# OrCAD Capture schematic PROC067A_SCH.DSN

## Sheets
1 07. HARDWARE SCHEMATICS: title: HARDWARE SCHEMATICS; rev: A; note: PROC066
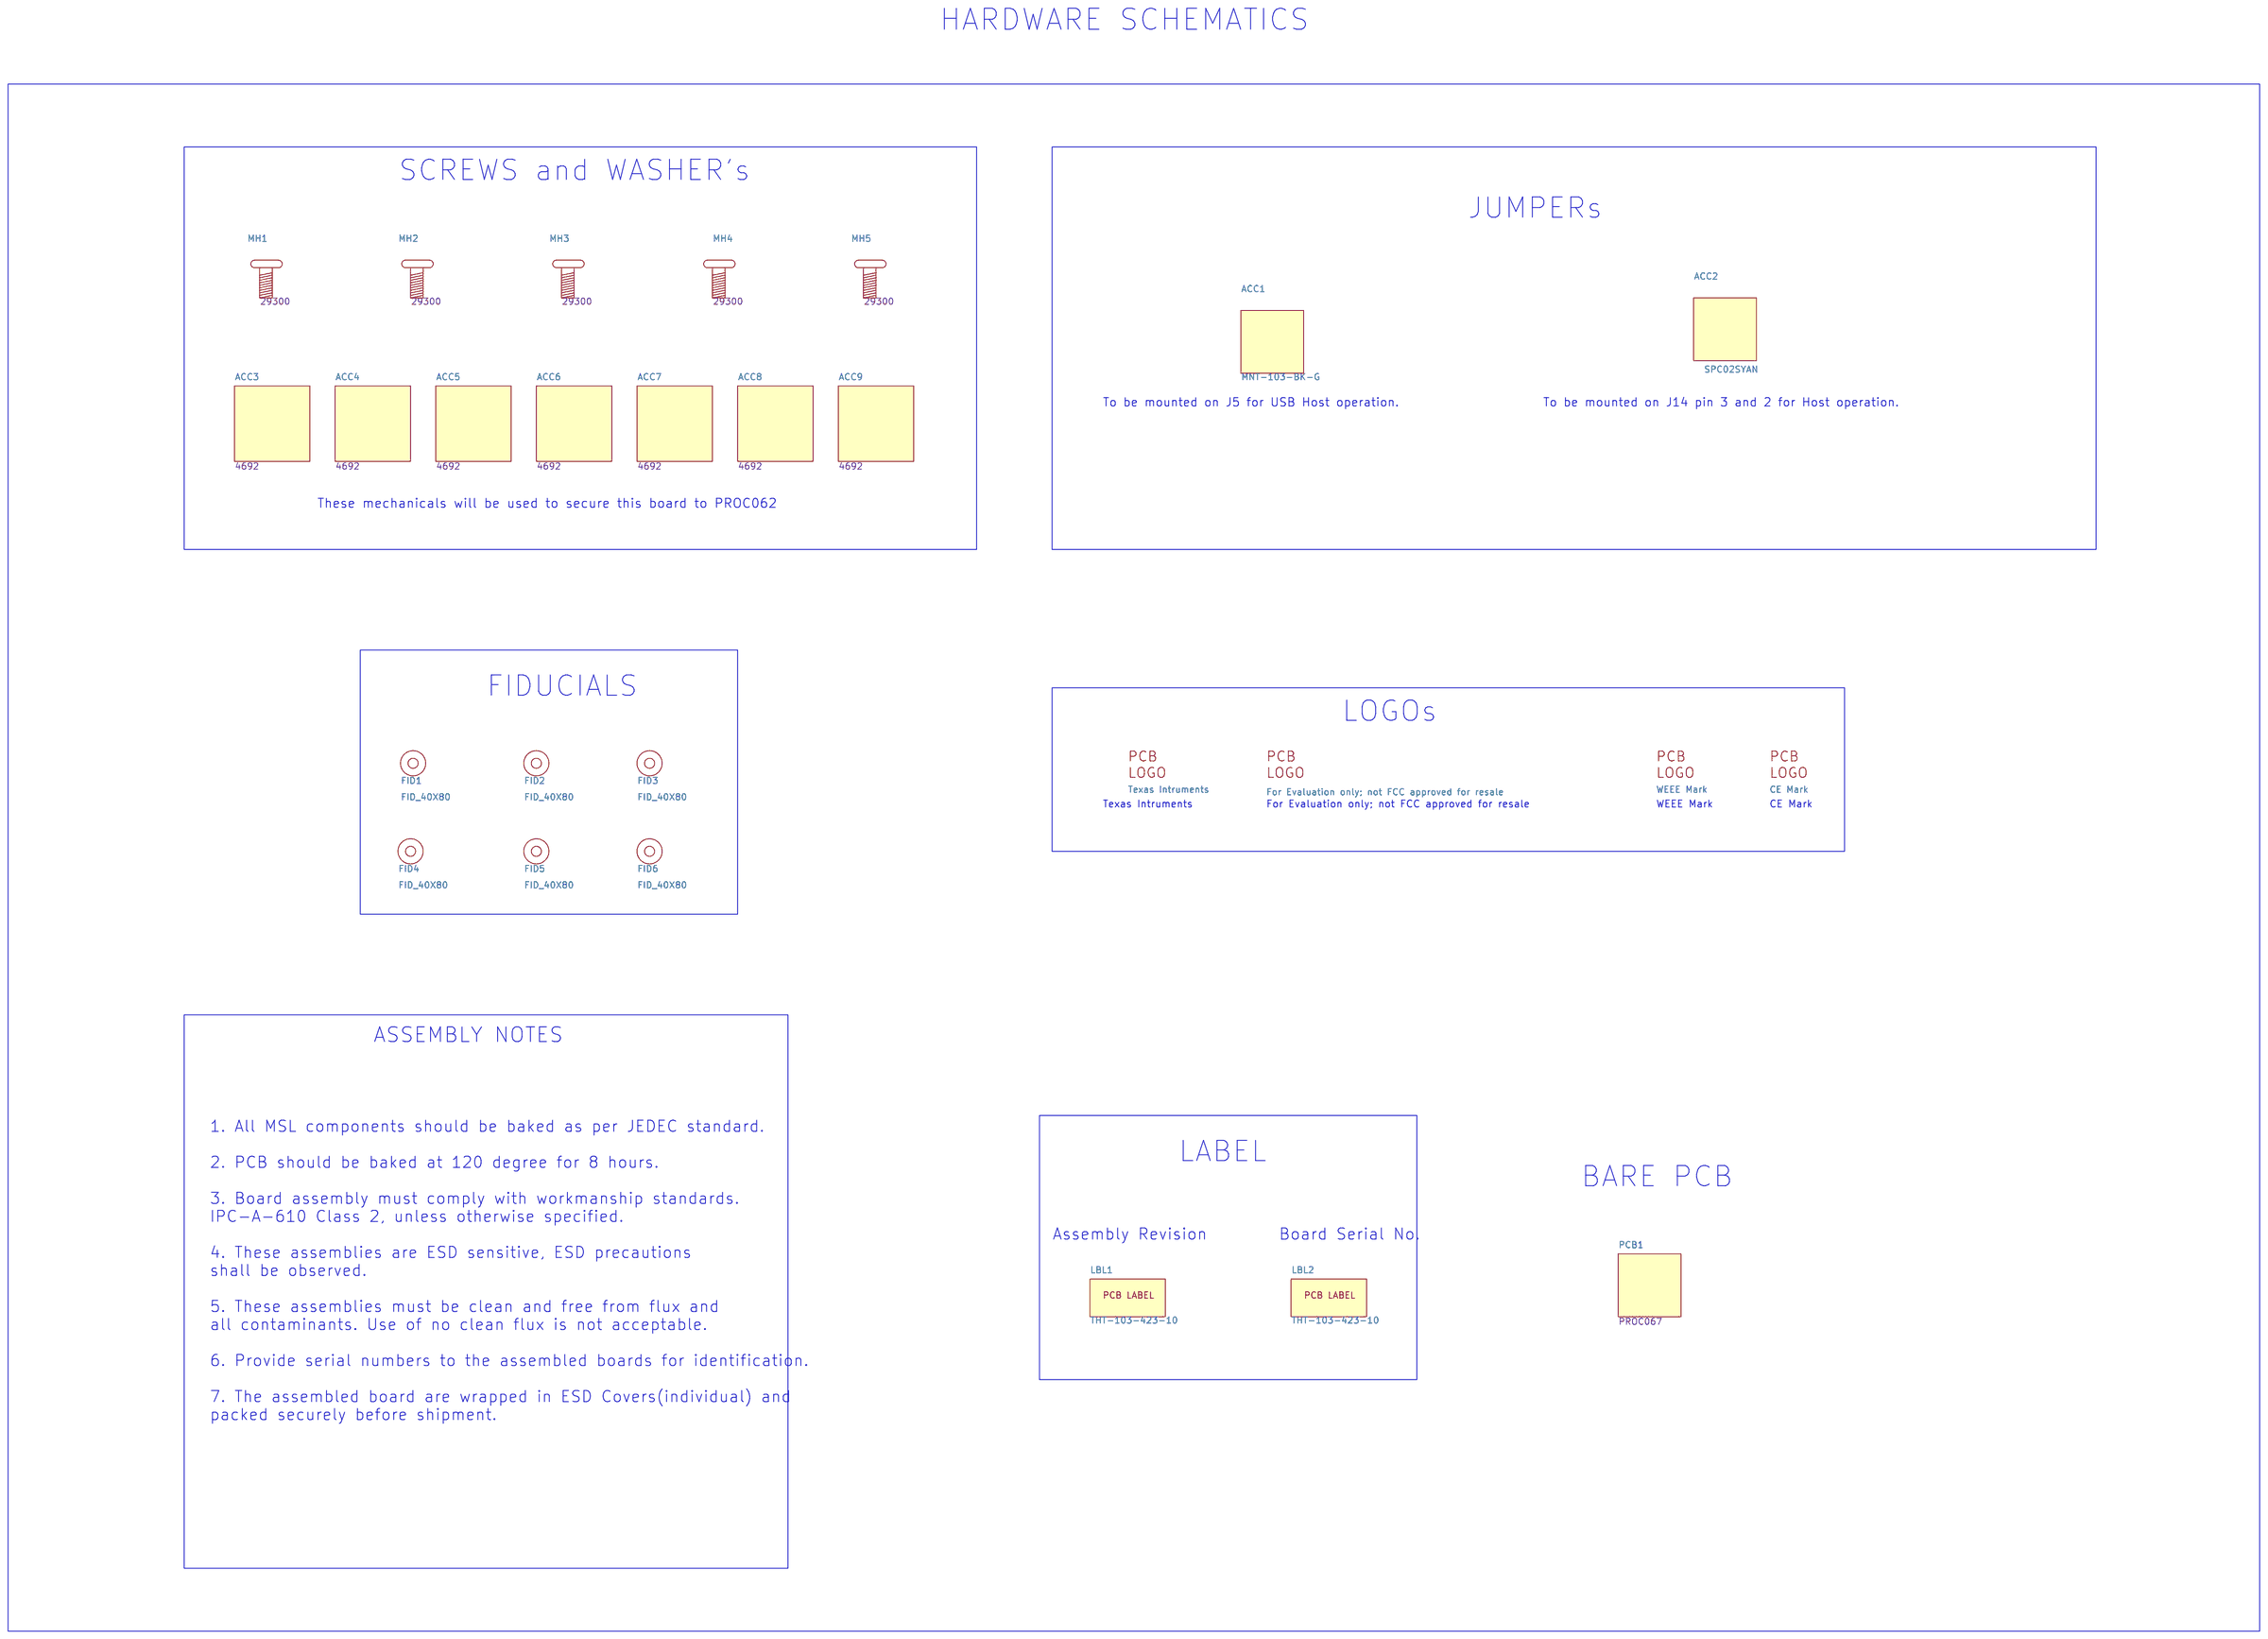
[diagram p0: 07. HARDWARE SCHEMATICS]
2 01. TABLE OF CONTENTS: title: TABLE OF CONTENTS; note: PROC067
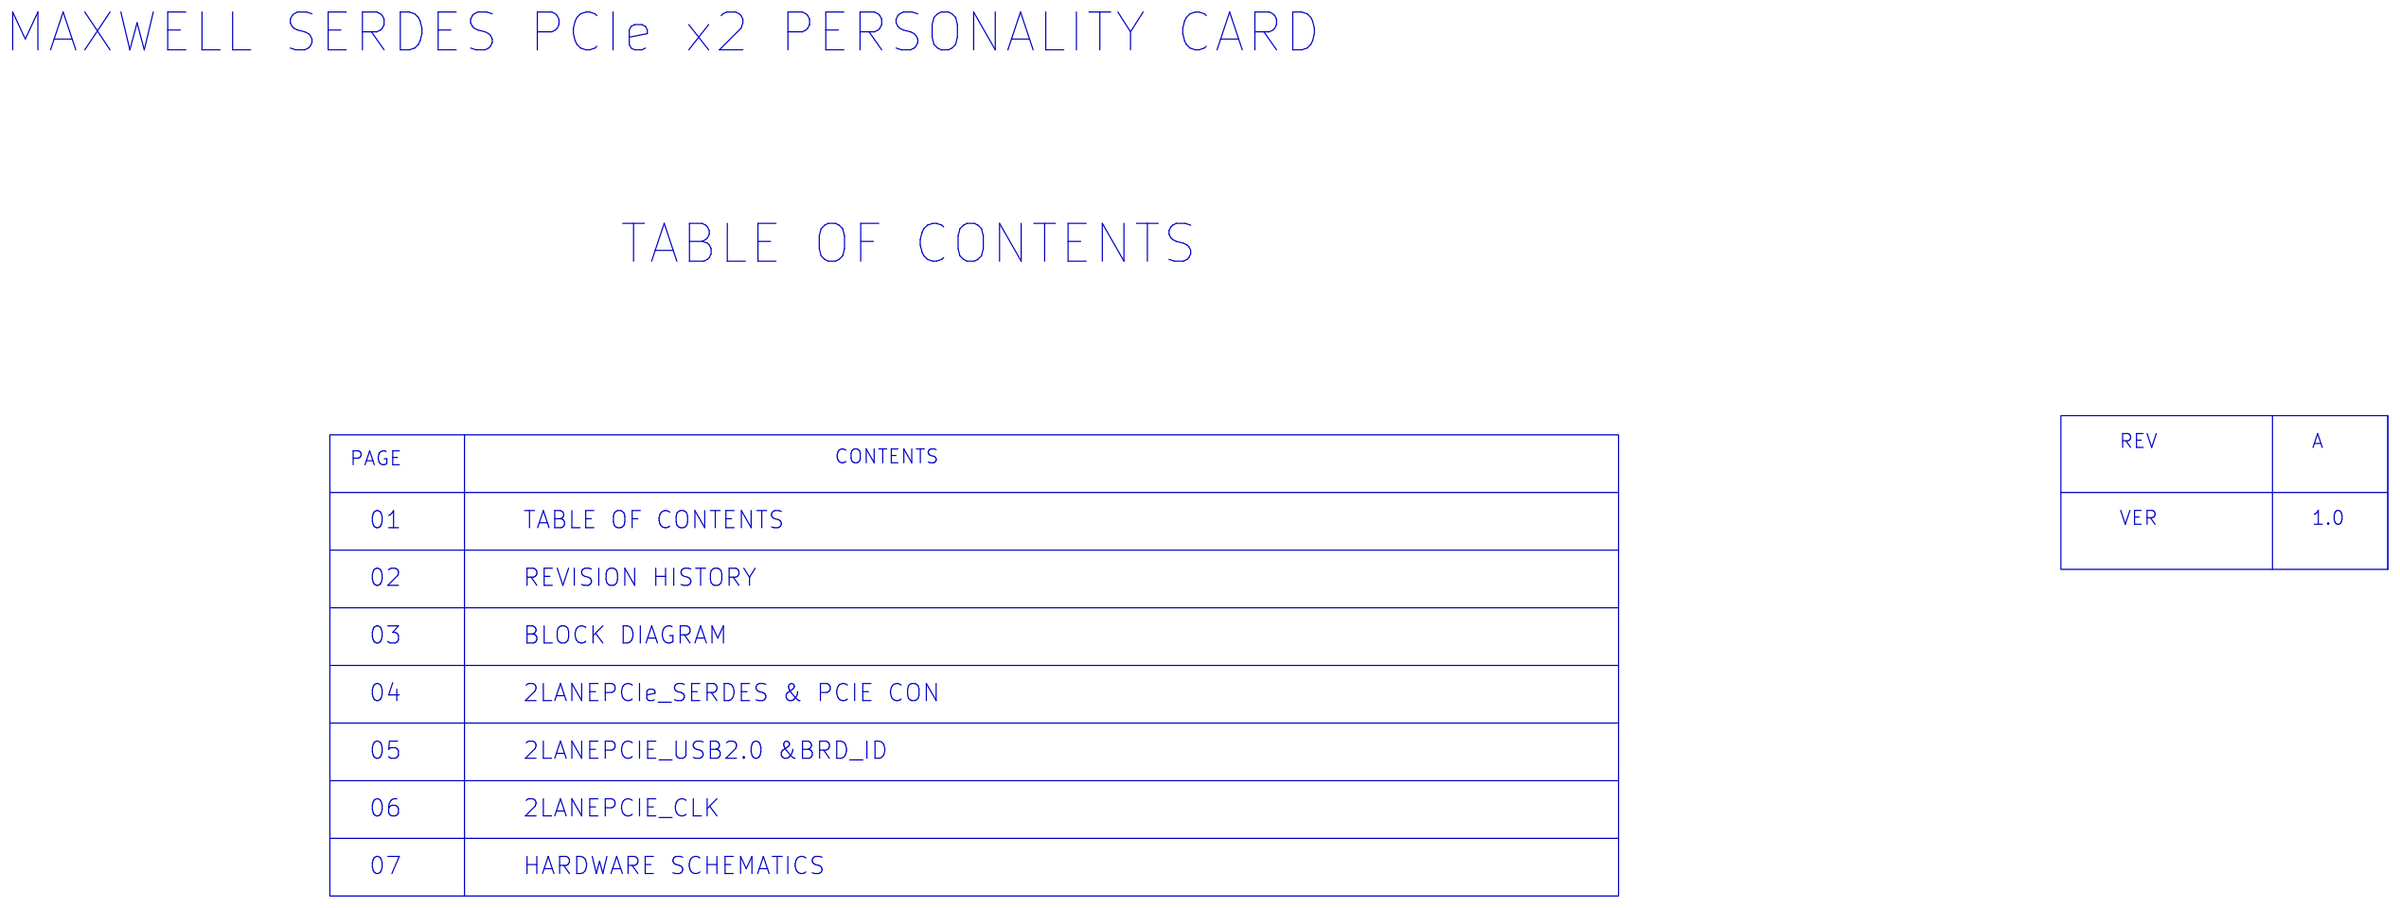
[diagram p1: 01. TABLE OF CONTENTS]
3 02. REVISION HISTORY: title: REVISION HISTORY; note: PROC067
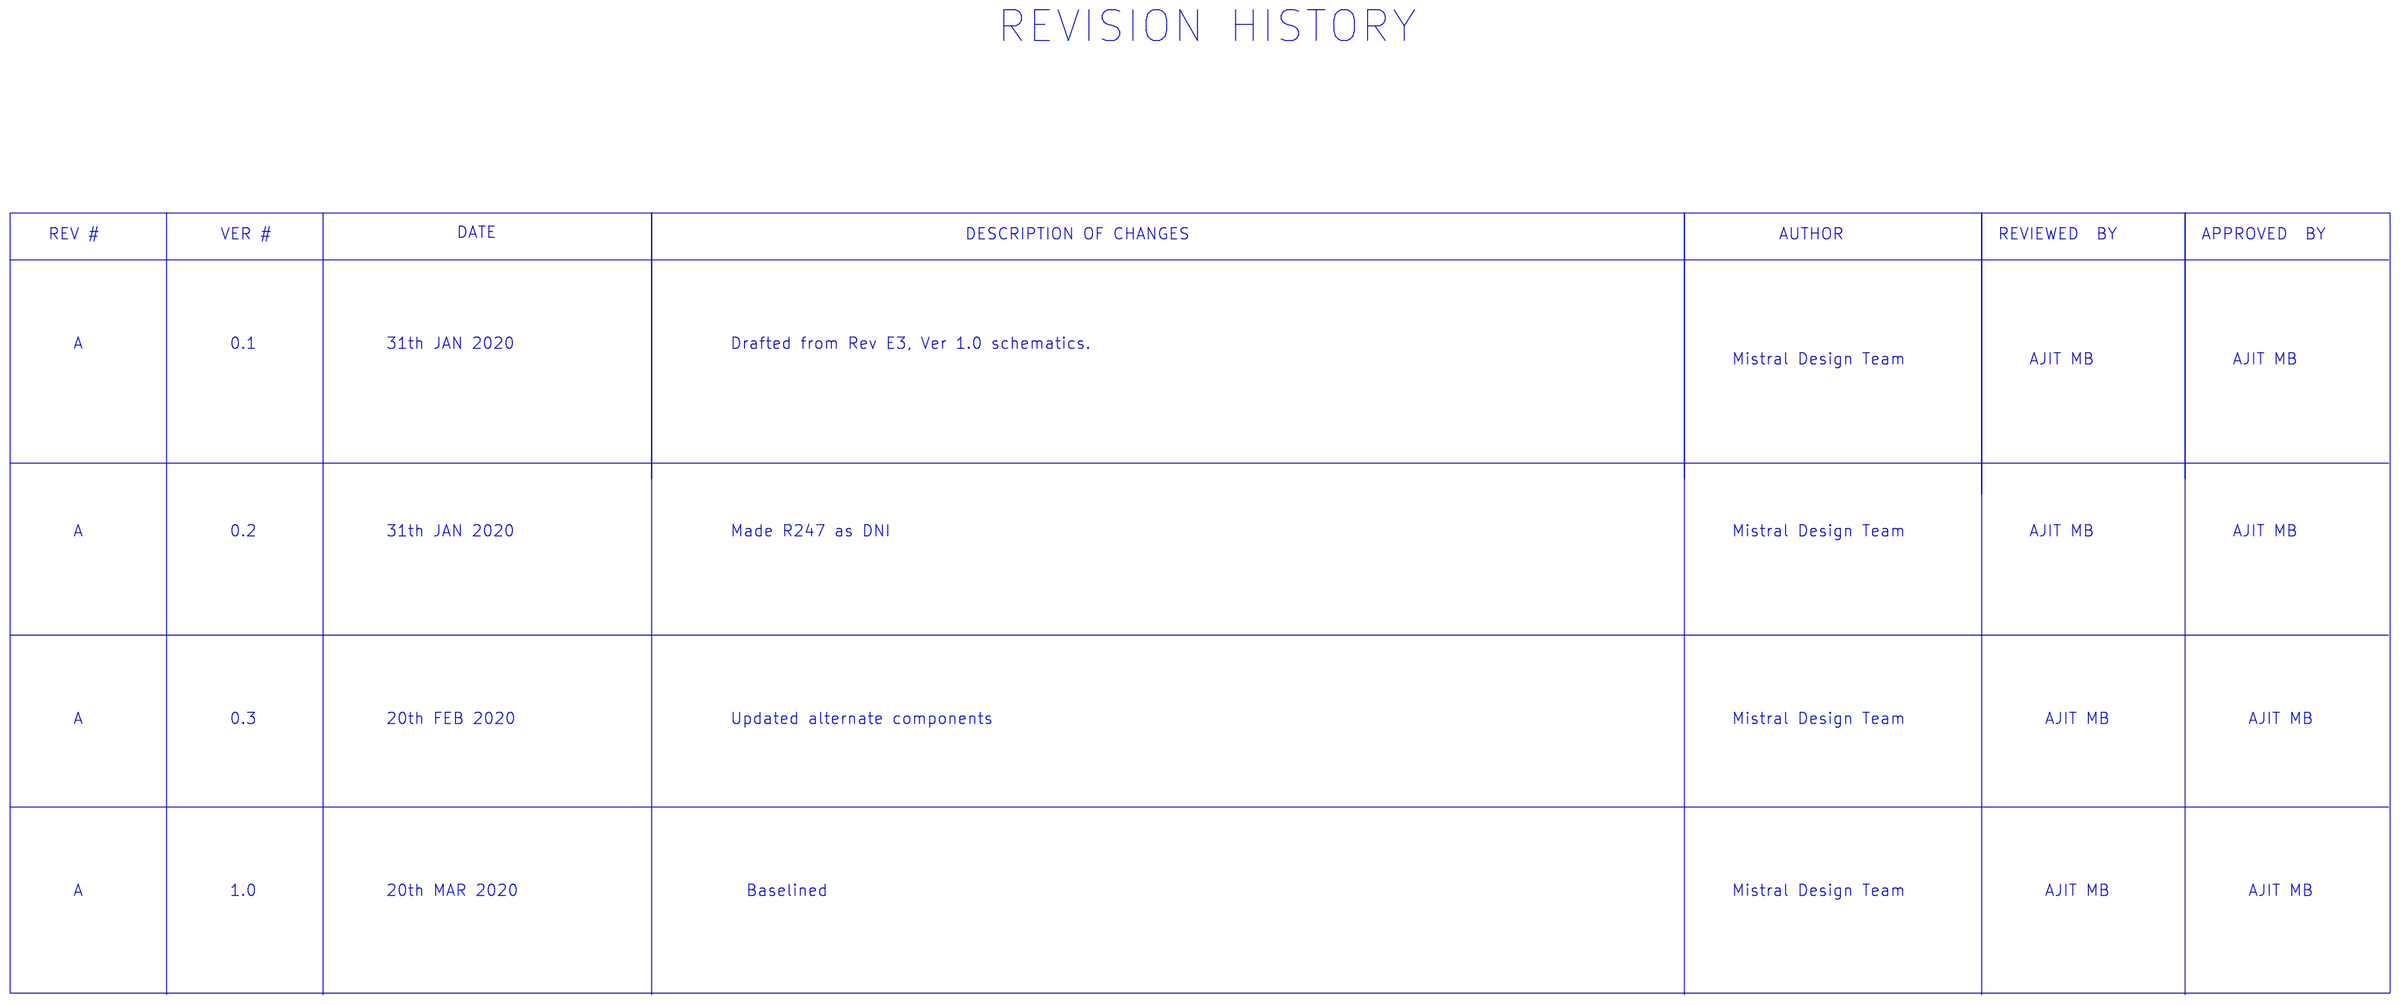
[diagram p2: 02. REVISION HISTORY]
4 03. BLOCK_DIAGRAM: title: BLOCK DIAGRAM; note: PROC067
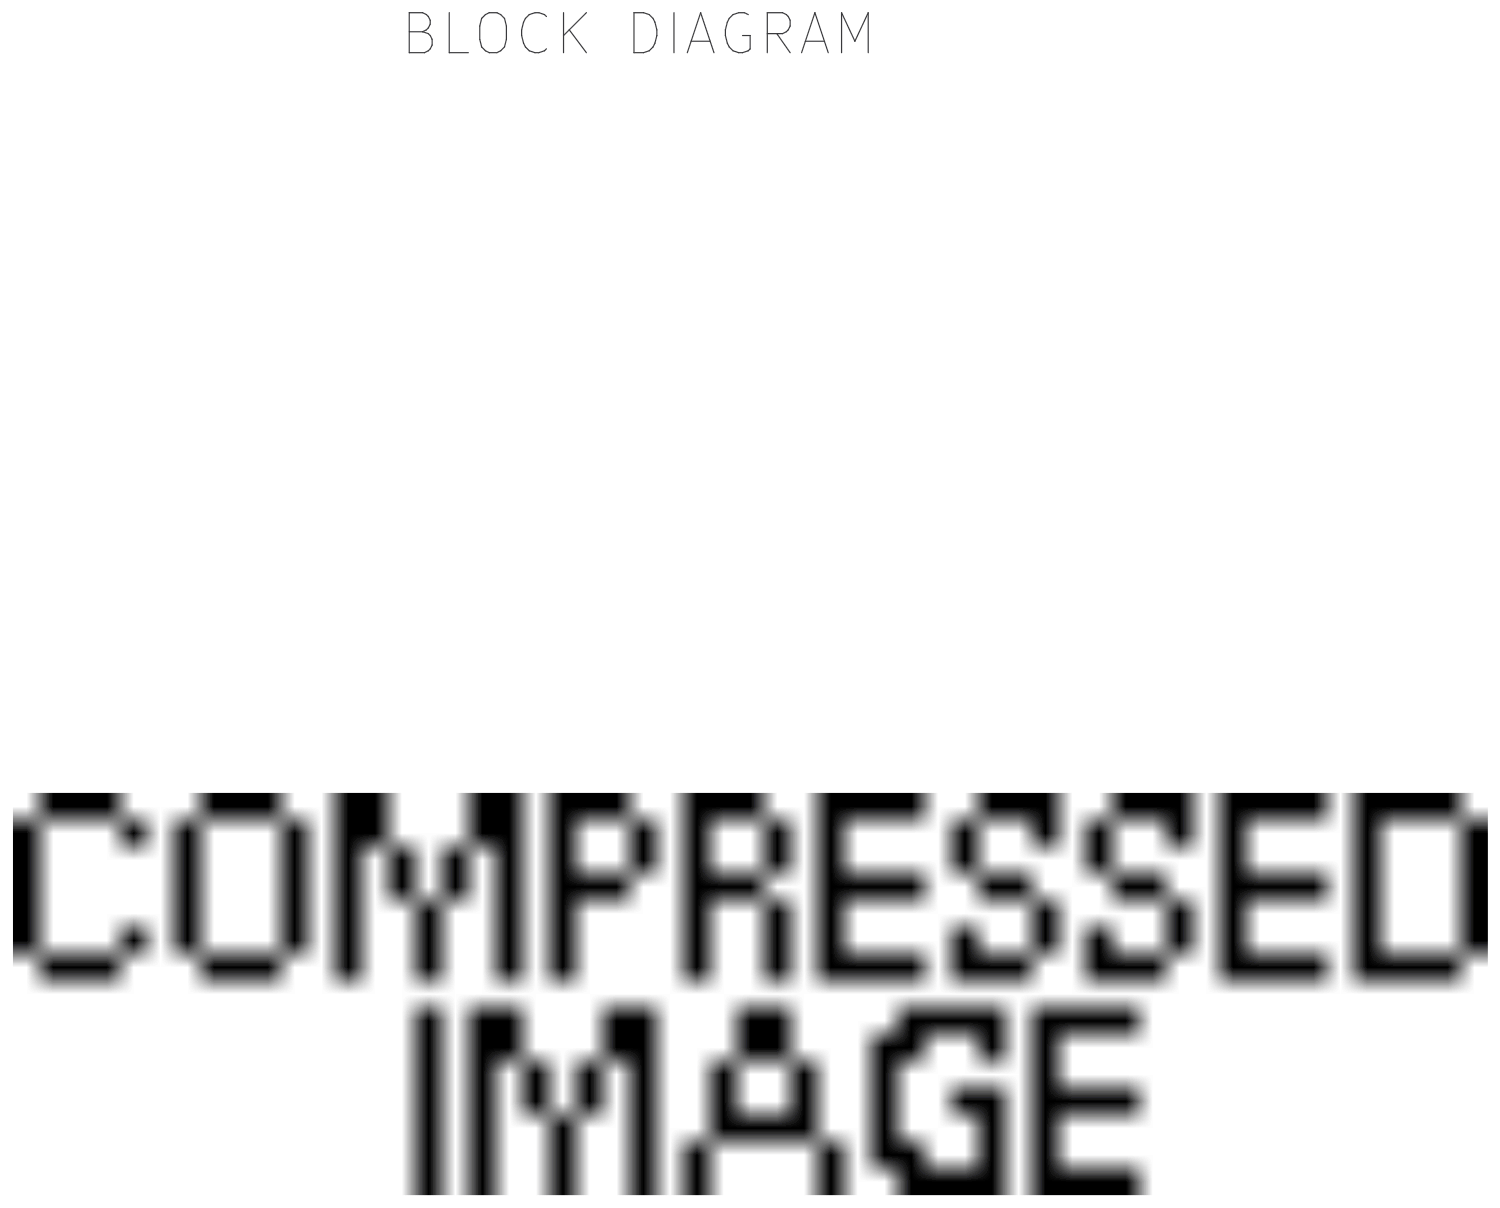
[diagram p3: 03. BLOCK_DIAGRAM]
5 04. 2LANEPCIe_SERDES & PCIE CON: size C; title: 2LANEPCIe_SERDES & PCIE CON; note: PROC067
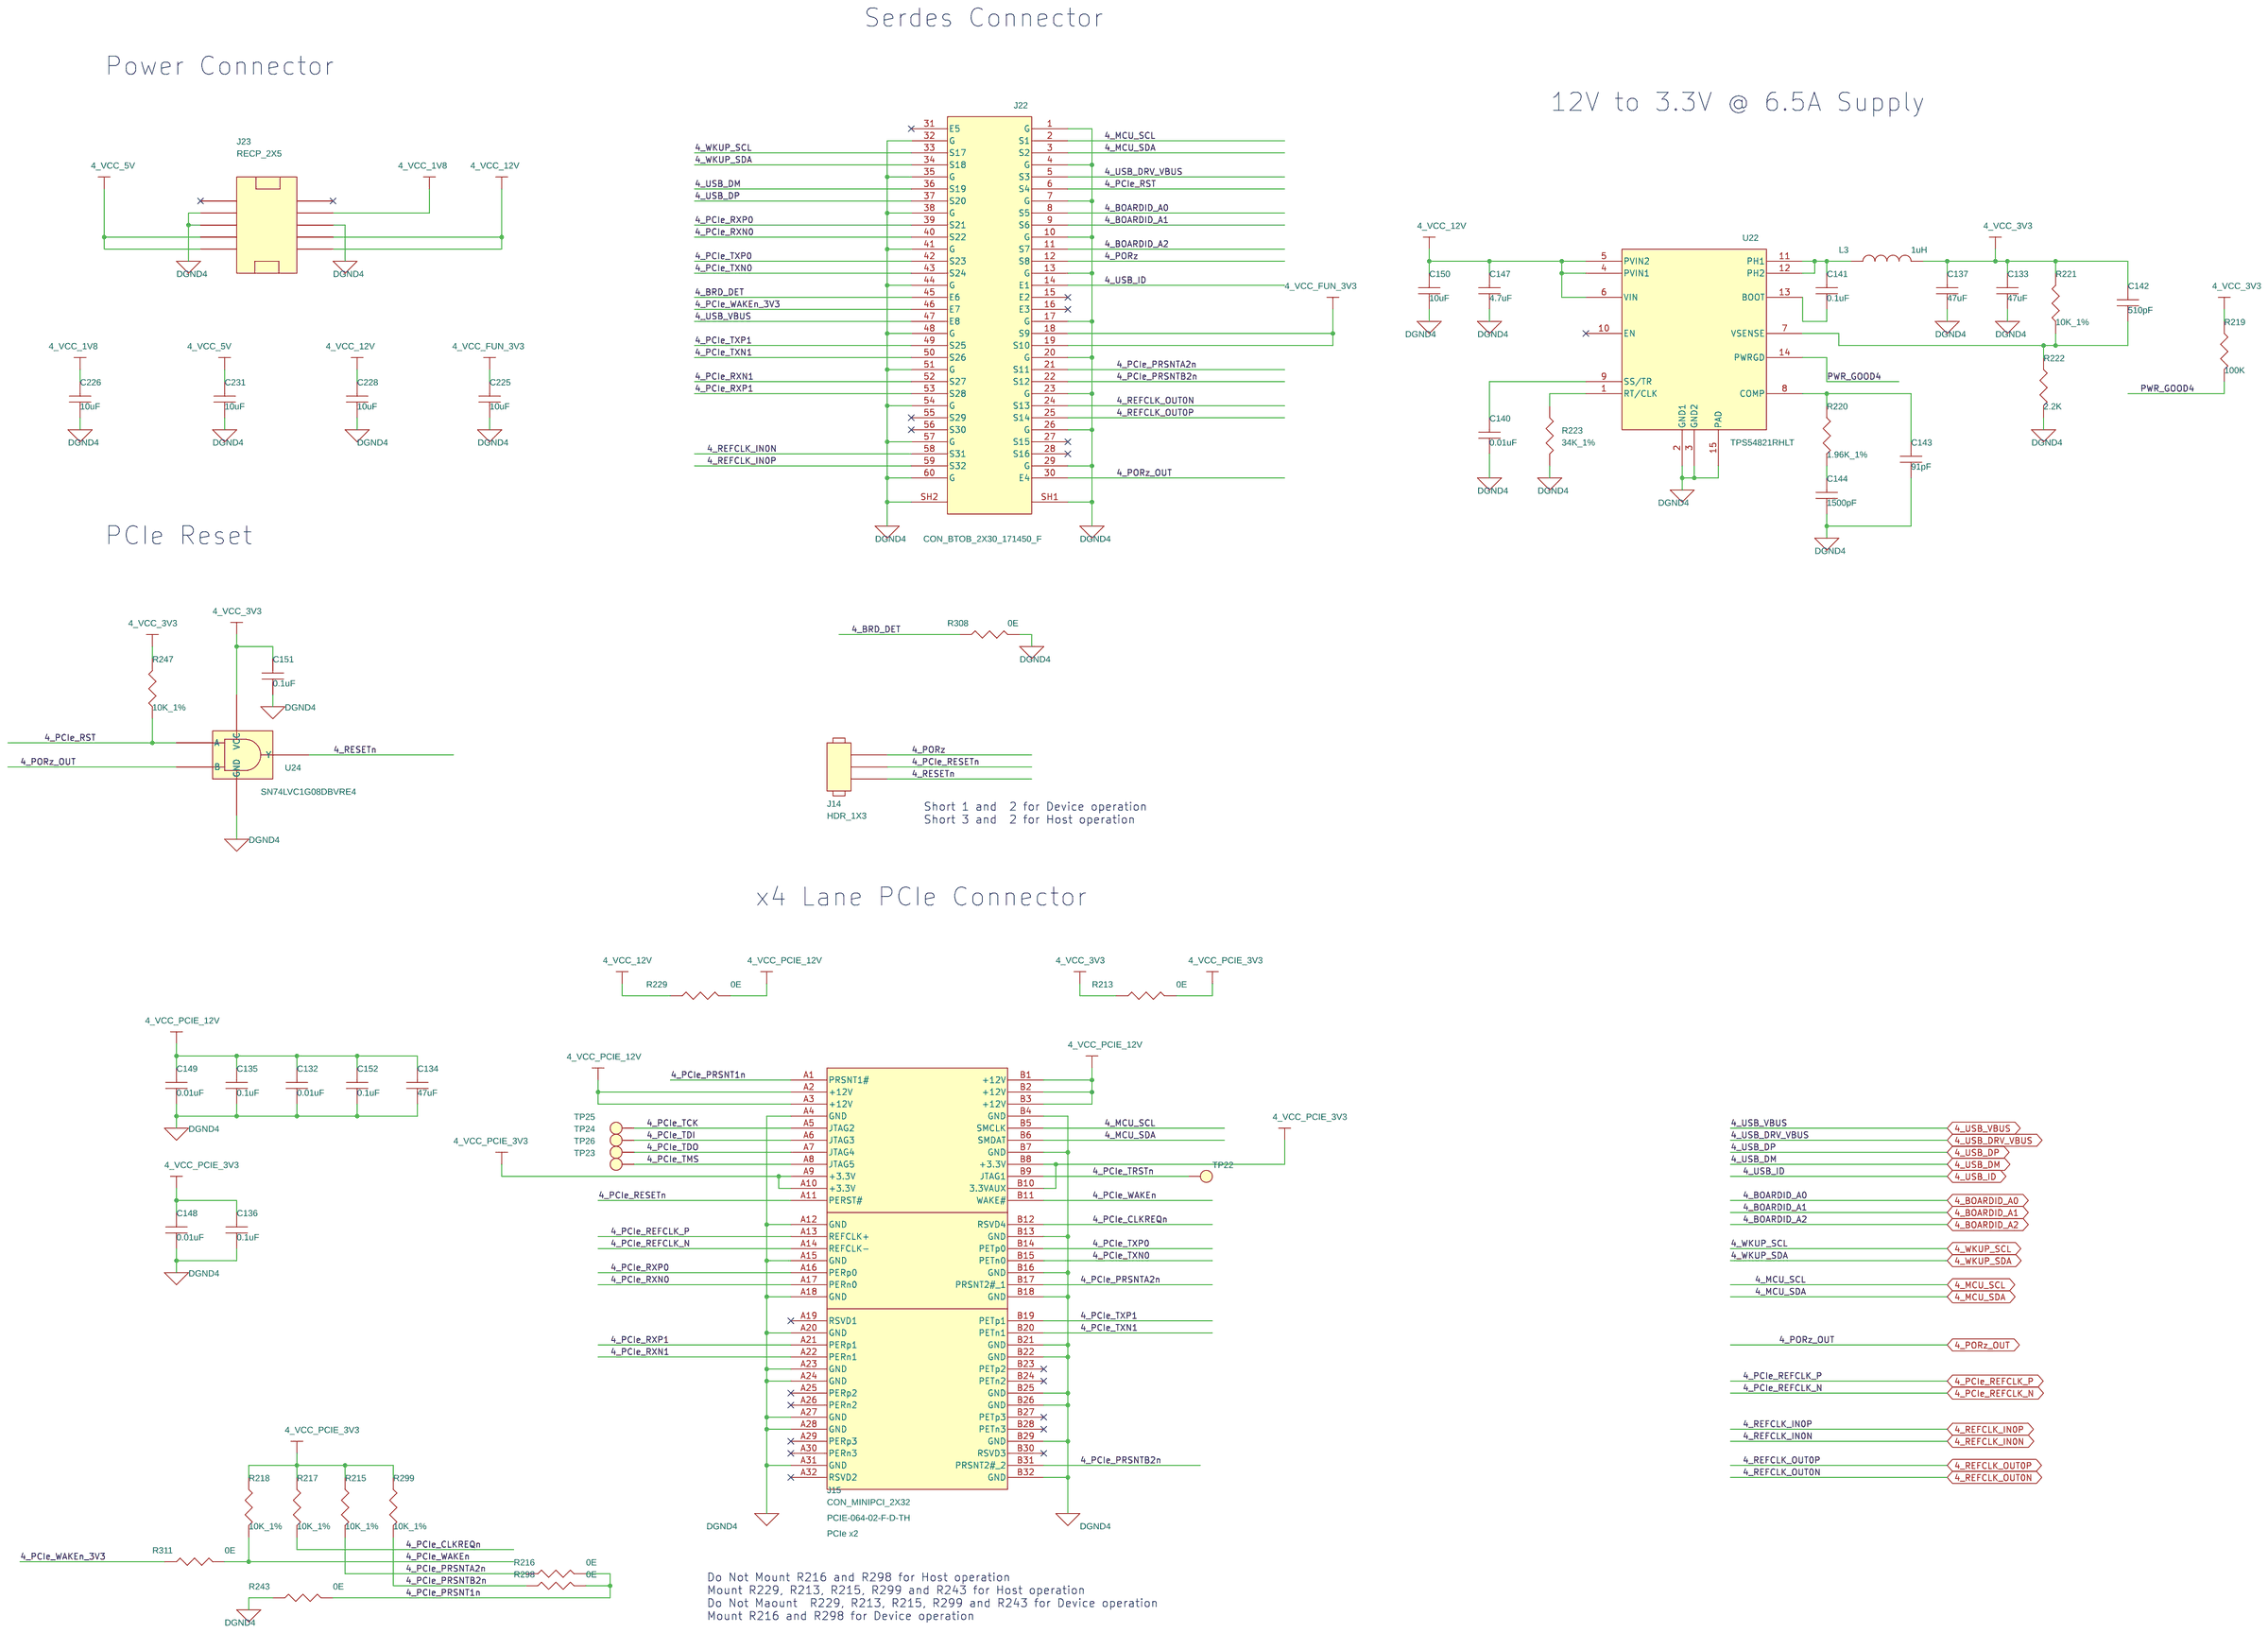
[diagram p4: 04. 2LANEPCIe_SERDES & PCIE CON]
6 05. 2LANEPCIE_USB2.0 &BRD_ID: size C; title: 2LANEPCIE_USB2.0 &BRD_ID; note: PROC067
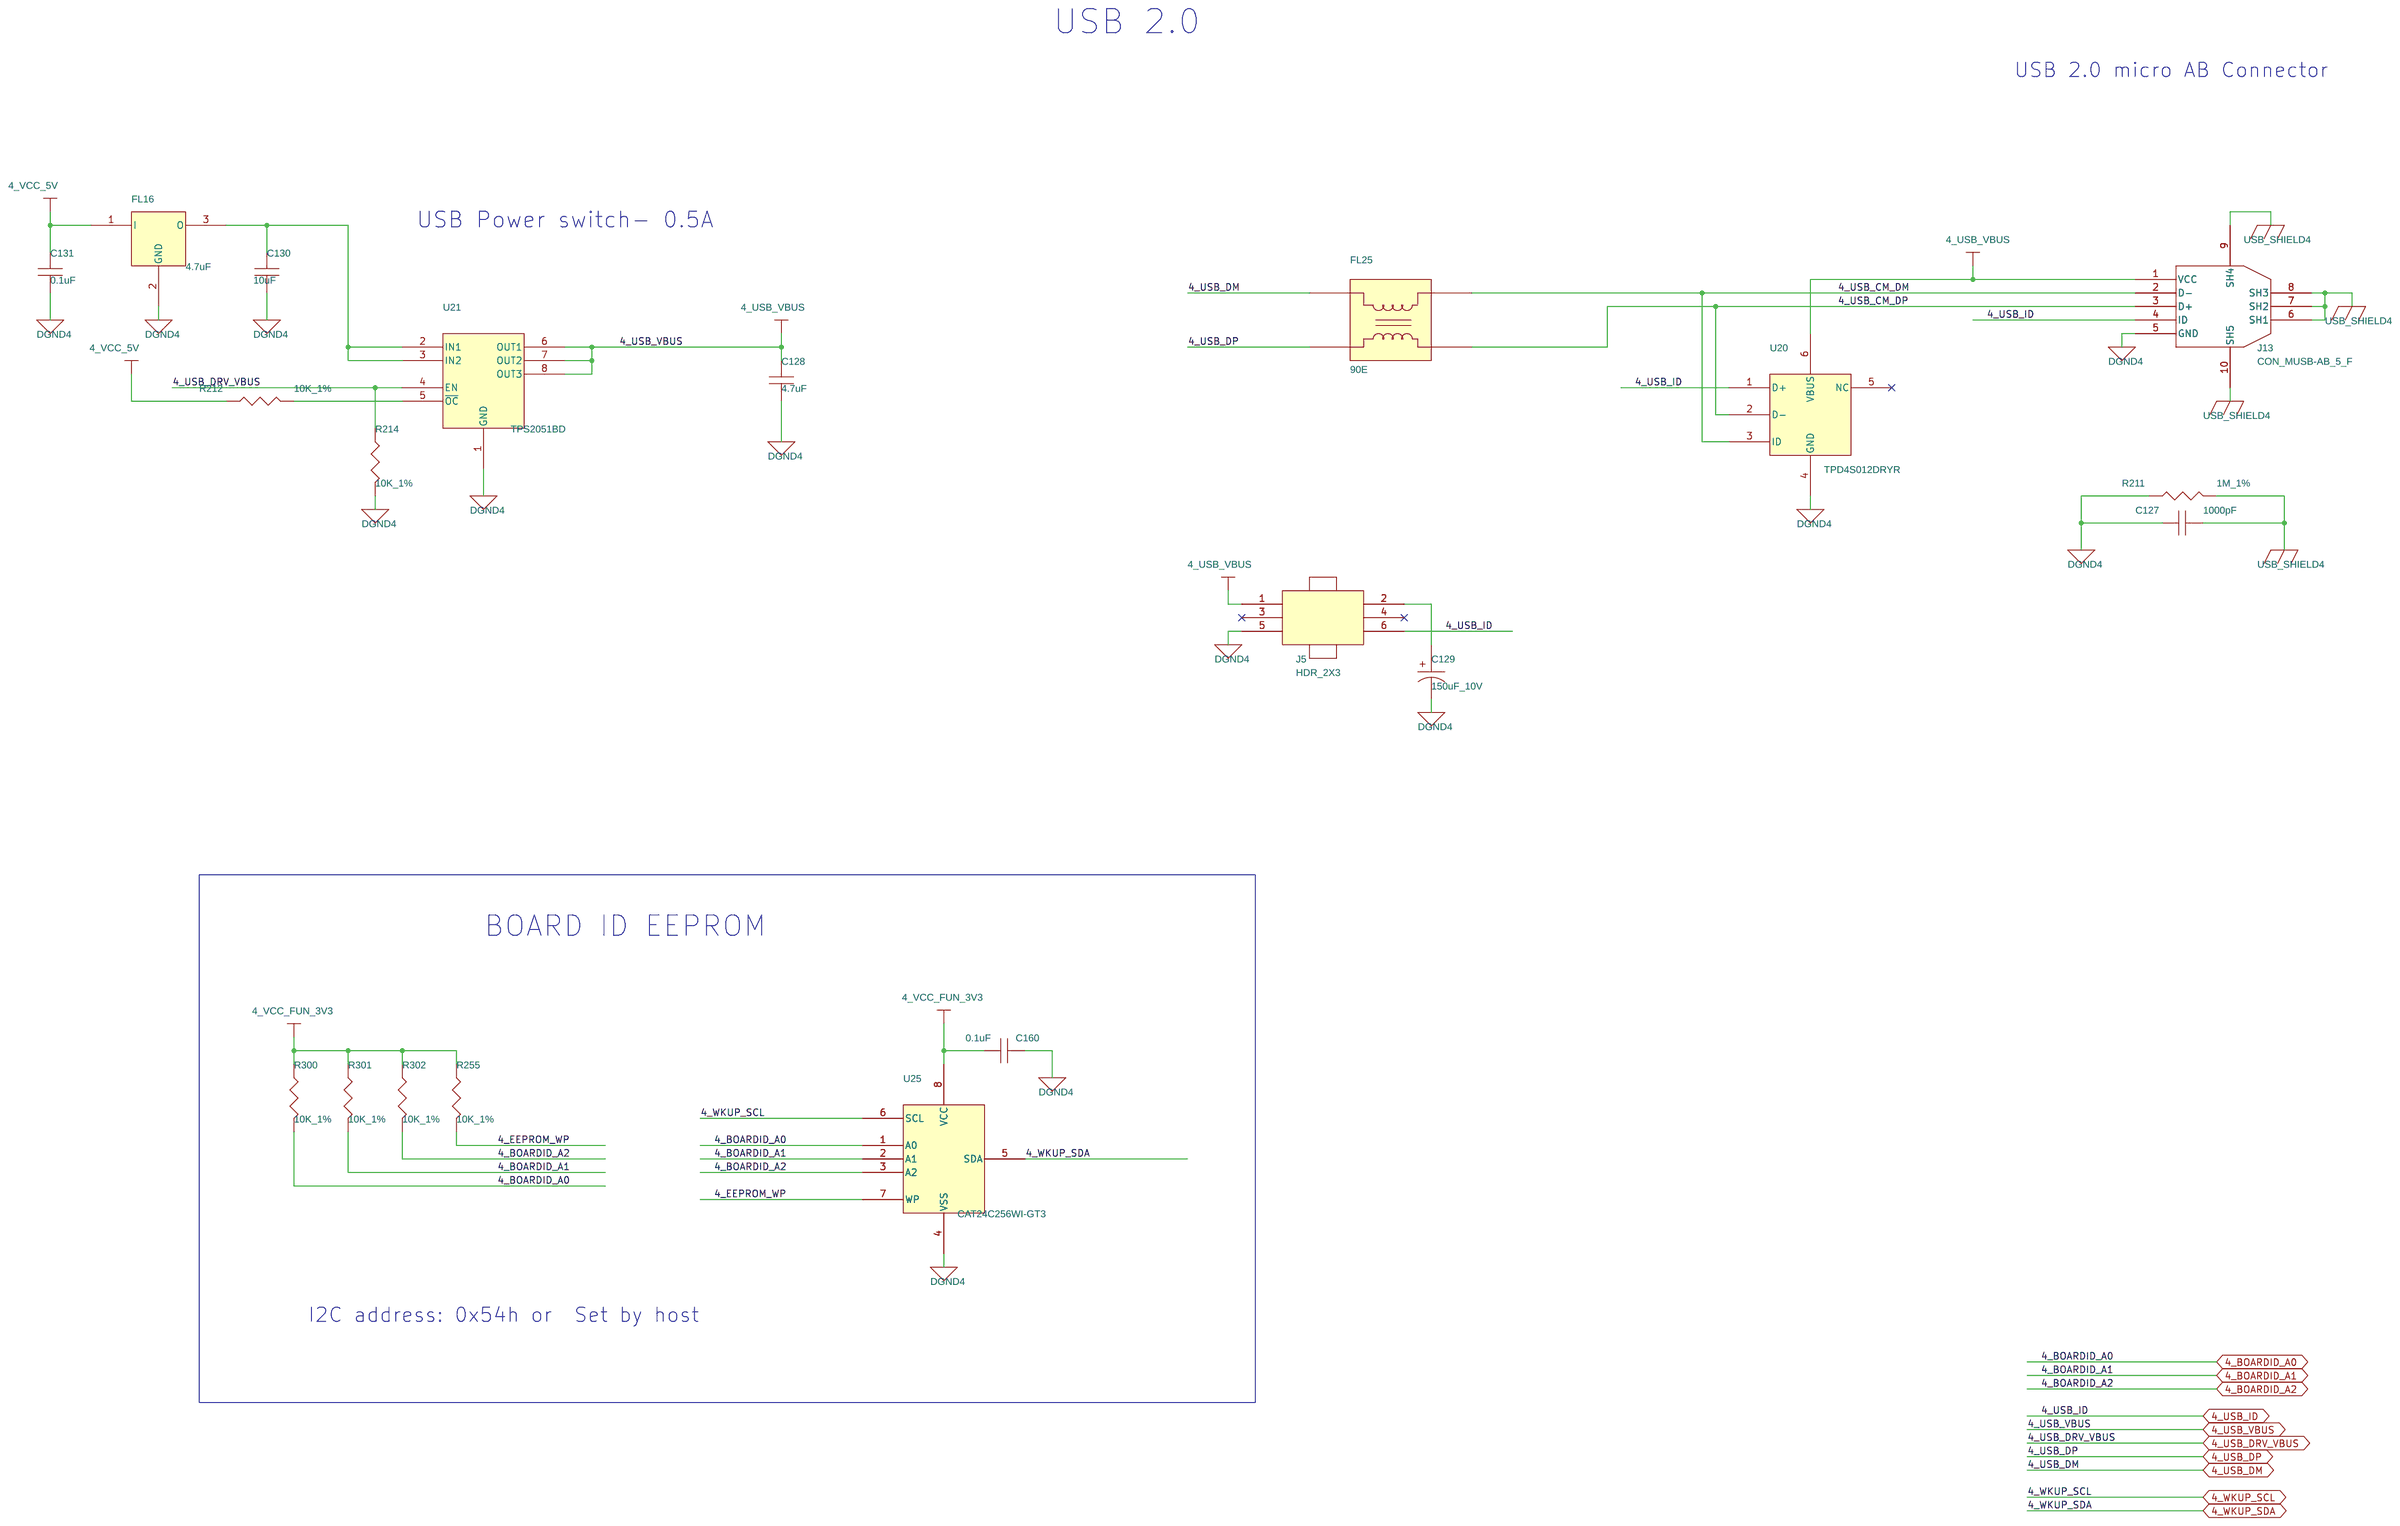
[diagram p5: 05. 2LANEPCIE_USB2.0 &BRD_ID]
7 06. 2LANEPCIE_CLK: size C; title: 2LANEPCIE_CLK; note: PROC067
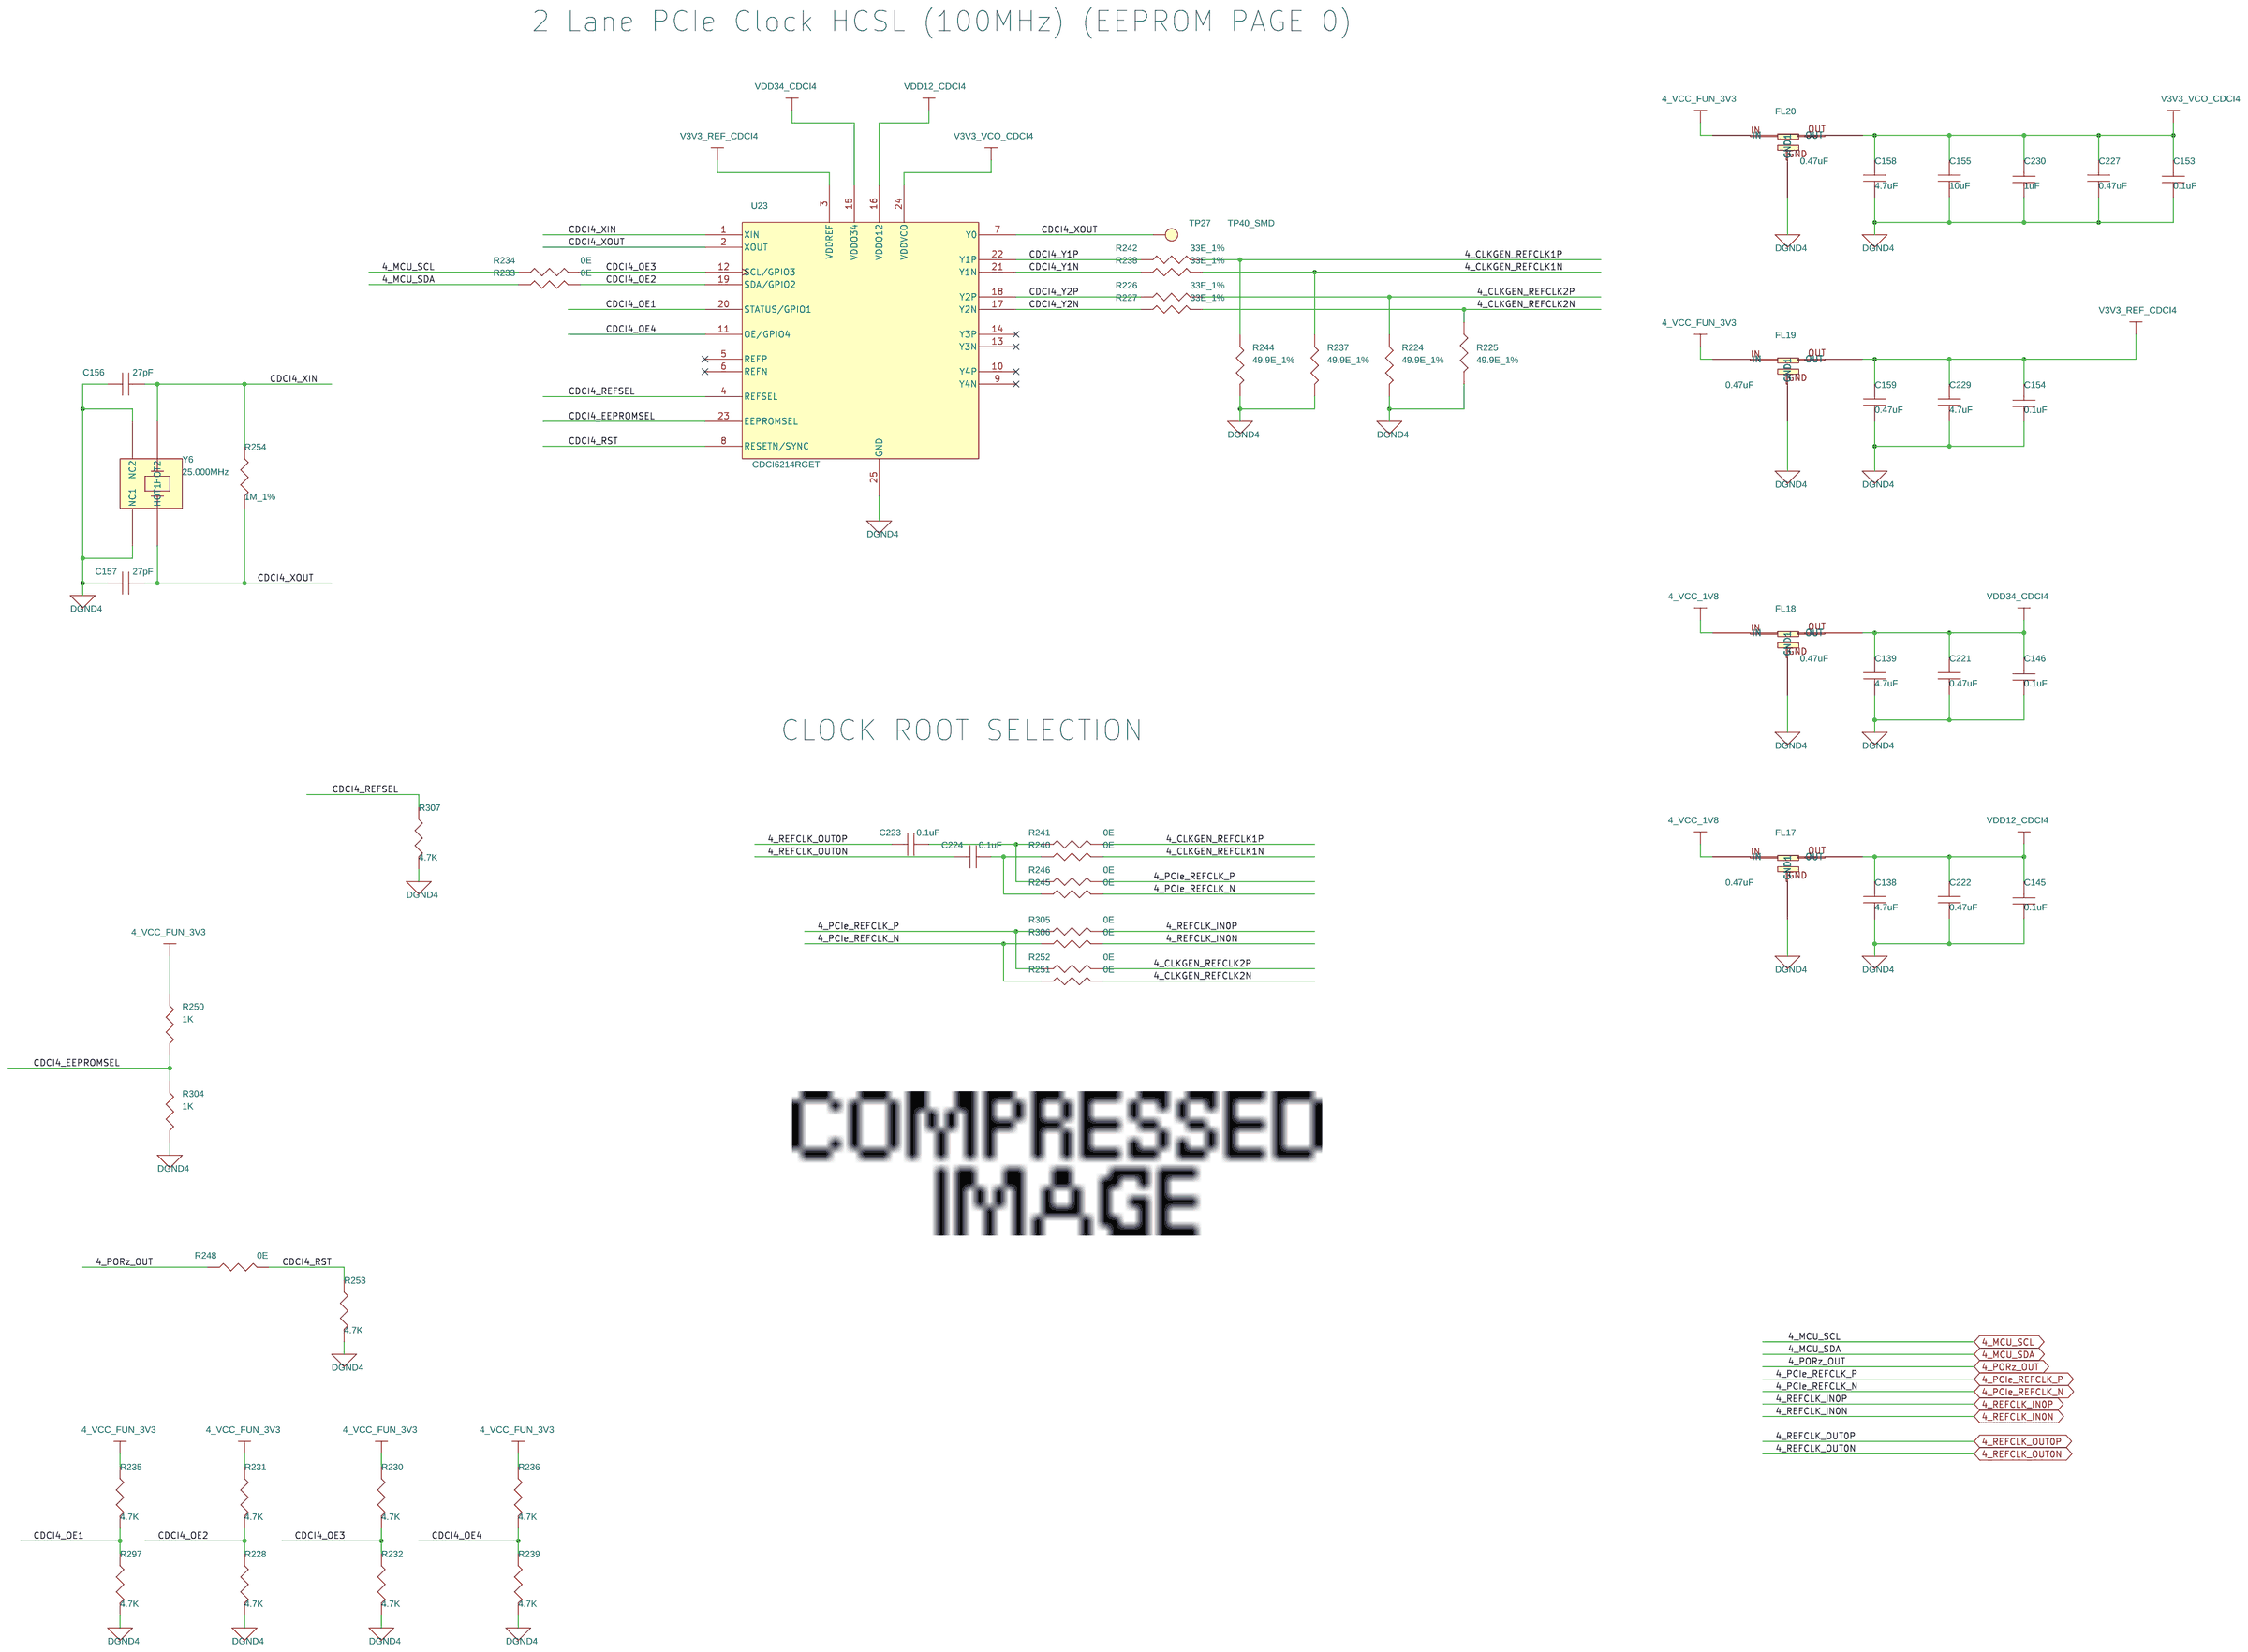
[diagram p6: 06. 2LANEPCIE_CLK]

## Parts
sheet 04. 2LANEPCIe_SERDES & PCIE CON
C132  0.01uF  [CAP0402]
C133  47uF  [CAP1206_2]
C134  47uF  [CAP1206_2]
C135  0.1uF  [CAP0402_0-75]
C136  0.1uF  [CAP0402_0-75]
C137  47uF  [CAP1206_2]
C140  0.01uF  [CAP0402]
C141  0.1uF  [CAP0402_0-75]
C142  510pF  [CAP0402_0-75]
C143  91pF  [CAP0402_0-75]
C144  1500pF  [CAP0402_0-75]
C147  4.7uF  [CAP1206]
C148  0.01uF  [CAP0402]
C149  0.01uF  [CAP0402]
C150  10uF  [CAP0603_1]
C151  0.1uF  [CAP0402_0-75]
C152  0.1uF  [CAP0402_0-75]
C225  10uF  [CAP0603_1]
C226  10uF  [CAP0603_1]
C228  10uF  [CAP0603_1]
C231  10uF  [CAP0603_1]
J14  HDR_1X3  [HDR_3X1_100_S_T]
J15  CON_MINIPCI_2X32  [CON_MINIPCI2X32_PCIE-064-02_S_S_T_11]
J22  CON_BTOB_2X30_171450_F  [CON_BTOB2X30_171450-5106_S_S_S_4-6]
J23  RECP_2X5  [RECPT_2X5_SFC-105-T1-D-A_S_T_4-6]
L3  1uH  [IND_XFL4020_170X170_SMD_2-1]
R213  0E  [RES1206_0-75]
R215  10K_1%  [RES0402_0-5]
R216  0E  [RES0402_0-5]
R217  10K_1%  [RES0402_0-5]
R218  10K_1%  [RES0402_0-5]
R219  100K  [RES0402_0-5]
R220  1.96K_1%  [RES0402]
R221  10K_1%  [RES0402_0-5]
R222  2.2K  [RES0402_0-5]
R223  34K_1%  [RES0402]
R229  0E  [RES1206_0-75]
R243  0E  [RES0402_0-5]
R247  10K_1%  [RES0402_0-5]
R298  0E  [RES0402_0-5]
R299  10K_1%  [RES0402_0-5]
R308  0E  [RES0402_0-5]
R311  0E  [RES0402_0-5]
TP22  TP40_SMD  [TP40_SMD]
TP23  TP40_SMD  [TP40_SMD]
TP24  TP40_SMD  [TP40_SMD]
TP25  TP40_SMD  [TP40_SMD]
TP26  TP40_SMD  [TP40_SMD]
U22  TPS54821RHLT  [QFN14_19-68_145X145]
U24  SN74LVC1G08DBVRE4  [SOT23-5]
sheet 05. 2LANEPCIE_USB2.0 &BRD_ID
C127  1000pF  [CAP1206]
C128  4.7uF  [CAP0402_0-75]
C129  150uF_10V  [CAPT7343D_3-25]
C130  10uF  [CAP0603_1]
C131  0.1uF  [CAP0402_0-75]
C160  0.1uF  [CAP0402_0-75]
FL16  4.7uF  [EMIFIL_NFM21P_0805_1]
FL25  90E  [IND4_ACM2012_90X50_SMD]
J5  HDR_2X3  [HDR_2X3_TSW-103-07-D_S_T_8-4]
J13  CON_MUSB-AB_5_F  [CON_USBAB5_475900001_S_R_S_3-1]
R211  1M_1%  [RES0402]
R212  10K_1%  [RES0402_0-5]
R214  10K_1%  [RES0402_0-5]
R255  10K_1%  [RES0402_0-5]
R300  10K_1%  [RES0402_0-5]
R301  10K_1%  [RES0402_0-5]
R302  10K_1%  [RES0402_0-5]
U20  TPD4S012DRYR  [SON6_19-68_40X60_PB_0-6]
U21  TPS2051BD  [SOIC8_1-8]
U25  CAT24C256WI-GT3  [SOIC8_1-8]
sheet 06. 2LANEPCIE_CLK
C138  4.7uF  [CAP0402_0-75]
C139  4.7uF  [CAP0402_0-75]
C145  0.1uF  [CAP0402_0-75]
C146  0.1uF  [CAP0402_0-75]
C153  0.1uF  [CAP0402_0-75]
C154  0.1uF  [CAP0402_0-75]
C155  10uF  [CAP0603_1]
C156  27pF  [CAP0402]
C157  27pF  [CAP0402]
C158  4.7uF  [CAP0402_0-75]
C159  0.47uF  [CAP0402_0-75]
C221  0.47uF  [CAP0402_0-75]
C222  0.47uF  [CAP0402_0-75]
C223  0.1uF  [CAP0402_0-75]
C224  0.1uF  [CAP0402_0-75]
C227  0.47uF  [CAP0402_0-75]
C229  4.7uF  [CAP0402_0-75]
C230  1uF  [CAP0402]
FL17  0.47uF  [EMIFIL_NFM21P_0805]
FL18  0.47uF  [EMIFIL_NFM21P_0805]
FL19  0.47uF  [EMIFIL_NFM21P_0805]
FL20  0.47uF  [EMIFIL_NFM21P_0805]
R224  49.9E_1%  [RES0402_0-5]
R225  49.9E_1%  [RES0402_0-5]
R226  33E_1%  [RES0402_0-5]
R227  33E_1%  [RES0402_0-5]
R228  4.7K  [RES0402]
R230  4.7K  [RES0402]
R231  4.7K  [RES0402]
R232  4.7K  [RES0402]
R233  0E  [RES0402_0-5]
R234  0E  [RES0402_0-5]
R235  4.7K  [RES0402]
R236  4.7K  [RES0402]
R237  49.9E_1%  [RES0402_0-5]
R238  33E_1%  [RES0402_0-5]
R239  4.7K  [RES0402]
R240  0E  [RES0402_0-5]
R241  0E  [RES0402_0-5]
R242  33E_1%  [RES0402_0-5]
R244  49.9E_1%  [RES0402_0-5]
R245  0E  [RES0402_0-5]
R246  0E  [RES0402_0-5]
R248  0E  [RES0402_0-5]
R250  1K  [RES0402_0-5]
R251  0E  [RES0402_0-5]
R252  0E  [RES0402_0-5]
R253  4.7K  [RES0402]
R254  1M_1%  [RES0402]
R297  4.7K  [RES0402]
R304  1K  [RES0402_0-5]
R305  0E  [RES0402_0-5]
R306  0E  [RES0402_0-5]
R307  4.7K  [RES0402]
TP27  TP40_SMD  [TP40_SMD]
U23  CDCI6214RGET  [QFN24_19-68_160X160_1]
Y6  25.000MHz  [XTAL4_NX3225GA_130X100_SMD]
sheet 07. HARDWARE SCHEMATICS
ACC1  MNT-103-BK-G  [NA]
ACC2  SPC02SYAN  [NA]
ACC3  PLAIN WASHER_M3  [NA]
ACC4  PLAIN WASHER_M3  [NA]
ACC5  PLAIN WASHER_M3  [NA]
ACC6  PLAIN WASHER_M3  [NA]
ACC7  PLAIN WASHER_M3  [NA]
ACC8  PLAIN WASHER_M3  [NA]
ACC9  PLAIN WASHER_M3  [NA]
FID1  FID_40X80  [FID_40X80]
FID2  FID_40X80  [FID_40X80]
FID3  FID_40X80  [FID_40X80]
FID4  FID_40X80  [FID_40X80]
FID5  FID_40X80  [FID_40X80]
FID6  FID_40X80  [FID_40X80]
LBL1  THT-103-423-10  [NA]
LBL2  THT-103-423-10  [NA]
Logo1  Texas Intruments  [TI_Stacked_Overlay_Small]
Logo2  For Evaluation only; not FCC approved for resale  [FCC_disclaimer]
Logo3  WEEE Mark  [TI_Stacked_Overlay_Small]
Logo4  CE Mark  [TI_Stacked_Overlay_Small]
MH1  PAN HEAD_M2.5 X 4  [NA]
MH2  PAN HEAD_M2.5 X 4  [NA]
MH3  PAN HEAD_M2.5 X 4  [NA]
MH4  PAN HEAD_M2.5 X 4  [NA]
MH5  PAN HEAD_M2.5 X 4  [NA]
PCB1  AM6x PCIE-2 LANE SERDES CARD  [NA]

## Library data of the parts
C132 C140 C148 C149 = CAP: CAP CERAMIC 0.01uF 50V 10% X7R 0402; Alternate_mfr_name_A: MURATA; Alternate_mfr_part_number_A: GRM155R71H103KA88D; Chkd/date: SHREESHAIL/301105; Crtd /date: MAZHAR/040505; Custom_Duty: 15%; Customs_HS_Code: 85322990; Distributor_name: DIGIKEY; Distributor_name_A: DIGIKEY; Distributor_part_number: 399-3066-1-ND; Distributor_part_number_A: 490-4516-1-ND; Height: 0.55MM; Mfr_name: KEMET; Mfr_part_number: C0402C103K5RACTU; Mistral Part No: 120009030025-R; Package: 0402; Part_type: CAPACITORS\CERAMIC; Project: G4_SVGA; RoHS: RoHS; Tolerance: 10%; Voltage: 50V; Datasheet: Y:\MIS_DATABASE\DATASHEETS\CAPACITORS\KEMET-C08.PDF
C133 C134 C137 = CAP: CAP CERAMIC 47uF 25V 20% X5R 1206; Chkd/date: MANIRAJA/230118; Crtd /date: MANIRAJA/230118; Custom_Duty: 15%; Customs_HS_Code: 85322990; Distributor_name: DIGIKEY; Distributor_part_number: 490-16268-1-ND; Height: 1.80MM; Mfr_name: MURATA; Mfr_part_number: GRM31CR61E476ME44L; Mistral Part No: 120013050002-R; Package: 1206; Part_type: CAPACITORS\CERAMIC; Project: TI_MAXIE_CPB; RoHS: RoHS; Temperature: -55°C+85°C; Tolerance: 20%; Voltage: 25V; Wattage: NA; Weight: NA; Datasheet: Y:\MIS_DATABASE\DATASHEETS\CAPACITORS\GRM31.PDF
C131 C135 C136 C141 C145 C146 C151-C154 C160 = CAP: CAP CERAMIC 0.1uF 25V 10% X5R 0402; Chkd/date: MANIRAJA/190220; Crtd /date: ALVY/190220; Custom_Duty: 15%; Customs_HS_Code: 85322990; Distributor_name: DIGIKEY; Distributor_part_number: 311-1697-1-ND; Footprint Path: Y:\MIS_DATABASE\Library\ALTIUM_TOOL\PCB_FOOTPRINTS\Altium_Footprint_Lib.PcbLib; Height: 0.55MM; Library Path: Y:\MIS_DATABASE\Library\ALTIUM_TOOL\SCHEMATICS_PARTS\MS_DISCRETE_Library.schlib; Mfr_name: YAGEO AMERICA; Mfr_part_number: CC0402KRX5R8BB104; Mistral Part No: 120017080016-R; Package: 0402; Part_type: CAPACITORS\CERAMIC; Project: TI_MAXIE_CPB; RoHS: RoHS; Temperature: -55°C+85°C; Tolerance: 10%; Voltage: 25V; Wattage: NA; Weight: 0.65mg; Datasheet: Y:\MIS_DATABASE\DATASHEETS\CAPACITORS\YACC-X5R.PDF
C142 = CAP: CAP CERAMIC 510pF 50V 5% C0G(NP0) 0402; Chkd/date: MANIRAJA/190220; Crtd /date: ALVY/190220; Custom_Duty: 15%; Customs_HS_Code: 85322990; Distributor_name: DIGIKEY; Distributor_part_number: 399-9955-1-ND; Footprint Path: Y:\MIS_DATABASE\Library\ALTIUM_TOOL\PCB_FOOTPRINTS\Altium_Footprint_Lib.PcbLib; Height: 0.55MM; Library Path: Y:\MIS_DATABASE\Library\ALTIUM_TOOL\SCHEMATICS_PARTS\MS_DISCRETE_Library.schlib; Mfr_name: KEMET; Mfr_part_number: C0402C511J5GAC7867; Mistral Part No: 120020020014-R; Package: 0402; Part_type: CAPACITORS\CERAMIC; Project: TI_MAXIE_CPB; RoHS: RoHS; Temperature: -55°C+125°C; Tolerance: 5%; Voltage: 50V; Wattage: NA; Weight: 0.65mg; Datasheet: Y:\MIS_DATABASE\DATASHEETS\CAPACITORS\KEMET-C0G_SERIES.PDF
C143 = CAP: CAP CERAMIC 91pF 50V 5% C0G(NP0) 0402; Chkd/date: MANIRAJA/190220; Crtd /date: ALVY/190220; Custom_Duty: 15%; Customs_HS_Code: 85322990; Distributor_name: DIGIKEY; Distributor_part_number: 311-3756-1-ND; Footprint Path: Y:\MIS_DATABASE\Library\ALTIUM_TOOL\PCB_FOOTPRINTS\Altium_Footprint_Lib.PcbLib; Height: 0.55MM; Library Path: Y:\MIS_DATABASE\Library\ALTIUM_TOOL\SCHEMATICS_PARTS\MS_DISCRETE_Library.schlib; Mfr_name: YAGEO AMERICA; Mfr_part_number: CC0402JRNPO9BN910; Mistral Part No: 120013050007-R; Package: 0402; Part_type: CAPACITORS\CERAMIC; Project: TI_MAXIE_CPB; RoHS: RoHS; Temperature: -55°C+125°C; Tolerance: 5%; Voltage: 50V; Wattage: NA; Weight: 0.65mg; Datasheet: Y:\MIS_DATABASE\DATASHEETS\CAPACITORS\YACC-NPO.PDF
C144 = CAP: CAP CERAMIC 1500pF 50V 10% X7R 0402; Chkd/date: MANIRAJA/190220; Crtd /date: ALVY/190220; Custom_Duty: 15%; Customs_HS_Code: 85322990; Distributor_name: DIGIKEY; Distributor_part_number: 311-1032-1-ND; Footprint Path: Y:\MIS_DATABASE\Library\ALTIUM_TOOL\PCB_FOOTPRINTS\Altium_Footprint_Lib.PcbLib; Height: 0.55MM; Library Path: Y:\MIS_DATABASE\Library\ALTIUM_TOOL\SCHEMATICS_PARTS\MS_DISCRETE_Library.schlib; Mfr_name: YAGEO AMERICA; Mfr_part_number: CC0402KRX7R9BB152; Mistral Part No: 120009030127-R; Package: 0402; Part_type: CAPACITORS\CERAMIC; Project: TI_MAXIE_CPB; RoHS: RoHS; Temperature: -55°C+125°C; Tolerance: 10%; Voltage: 50V; Wattage: NA; Weight: 12mg; Datasheet: Y:\MIS_DATABASE\DATASHEETS\CAPACITORS\YACC-X7R.PDF
C147 = CAP: CAP CERAMIC 4.7uF 25V 10% X5R 1206; Chkd/date: SHREESHAIL/291105; Crtd /date: MAZHAR/040505; Custom_Duty: 15%; Customs_HS_Code: 85322990; Distributor_name: DIGIKEY; Distributor_part_number: 478-1570-1-ND; Height: 1.50MM; Mfr_name: AVX CORPORATION; Mfr_part_number: 12063D475KAT2A; Mistral Part No: 120009030424-R; Package: 1206; Part_type: CAPACITORS\CERAMIC; Project: G4_SVGA; RoHS: RoHS; Tolerance: 10%; Voltage: 25V; Datasheet: Y:\MIS_DATABASE\DATASHEETS\CAPACITORS\AVX_MLC.PDF
C130 C150 C155 C225 C226 C228 C231 = CAP: CAP CERAMIC 10uF 25V 20% X5R 0603; Chkd/date: MANIRAJA/130617; Crtd /date: MUDDU/130810; Custom_Duty: 15%; Customs_HS_Code: 85322990; Distributor_name: DIGIKEY; Distributor_part_number: 490-7202-1-ND; Height: 0.90MM; Mfr_name: MURATA; Mfr_part_number: GRM188R61E106MA73D; Mistral Part No: 120010080005-R; Package: 0603; Part_type: CAPACITORS\CERAMIC; Project: PB_BUGBASE; RoHS: RoHS; Temperature: -55°C+85°C; Tolerance: 20%; Voltage: 25V; Wattage: NA; Weight: 6.3mg; Datasheet: Y:\MIS_DATABASE\DATASHEETS\CAPACITORS\MURATA_CMCC.PDF
J14 = HEADER_3X1: HDR 1X3 2.54MM PITCH ST TH; Chkd/date: VASANTHA/290616; Crtd /date: VASANTHA/290616; Custom_Duty: 15%; Customs_HS_Code: 85322990; Distributor_name: DIGIKEY; Distributor_part_number: 609-3471-ND; Height: 8.58MM; Mfr_name: FCI; Mfr_part_number: 68001-403HLF; Mistral Part No: 150016060025-R; Package: THRU-HOLE; Part_type: CONNECTOR\HEADERS; Project: IKEYP; RoHS: RoHS; TEXT: REST; TEXT1: INT; TEXT2: EXT; Temperature: -40°C+105°C; Tolerance: NA; Voltage: NA; Wattage: NA; Weight: NA; Datasheet: Y:\MIS_DATABASE\DATASHEETS\CONNECTORS\68000.PDF
J15 = CON_MINIPCI_32X2: CON MINIPCI 2X32 1.00MM PITCH SOCKET ST TH; Chkd/date: MANIRAJA/101017; Crtd /date: MANIRAJA/101017; Custom_Duty: 24%; Customs_HS_Code: 85369090; Distributor_name: DIGIKEY; Distributor_part_number: SAM9742-ND; Height: 11.00MM; Mfr_name: SAMTEC; Mfr_part_number: PCIE-064-02-F-D-TH; Mistral Part No: 150017100015-R; Package: THRU-HOLE; Part_type: CONNECTOR\PCI; Project: TI_SVB_MAXWELL_SPM; RoHS: RoHS; TEXT: PCIe x2; Temperature: -55°C+125°C; Tolerance: NA; Voltage: NA; Wattage: NA; Weight: NA; Datasheet: Y:\MIS_DATABASE\DATASHEETS\CONNECTORS\SAMTEC-PCIE-TH.PDF
J22 = CON_BTOB_30X2_171450: CON BTOB 2X30 0.80MM PITCH FEMALE ST SMD; Chkd/date: MANIRAJA/050319; Crtd /date: ALVY/050319; Custom_Duty: 24%; Customs_HS_Code: 85369090; Distributor_name: DIGIKEY; Distributor_part_number: 1714505106-ND; Footprint Path: Y:\MIS_DATABASE\Library\ALTIUM_TOOL\PCB_FOOTPRINTS\Altium_Footprint_Lib.PcbLib; Height: 4.60MM; Library Path: Y:\MIS_DATABASE\Library\ALTIUM_TOOL\SCHEMATICS_PARTS\MS_CONNECTOR_Library.schlib; Mfr_name: MOLEX; Mfr_part_number: 171450-5106; Mistral Part No: 150019030002-R; Package: SMD; Part_type: CONNECTOR\BTOB; Project: TI_J7ES_EVM_SOM; RoHS: RoHS; Temperature: -40°C+105°C; Tolerance: NA; Voltage: NA; Wattage: NA; Weight: 748mg; Datasheet: Y:\MIS_DATABASE\DATASHEETS\CONNECTORS\171450-51XX.PDF
J23 = RECP_5X2: CON RECP 2X5 1.27MM PITCH ST TH; Chkd/date: VASANTHA/181017; Crtd /date: VASANTHA/181017; Custom_Duty: 24%; Customs_HS_Code: 85369090; Distributor_name: NA; Distributor_part_number: NA; Height: 4.57MM; Mfr_name: SAMTEC; Mfr_part_number: SFC-105-T1-L-D-A; Mistral Part No: 150017100028-R; Package: THRU-HOLE; Part_type: CONNECTOR\RECEPTACLE; Project: TI_MAXIE_CPB; RoHS: RoHS; TEXT: POWER; Temperature: -55°C+125°C; Tolerance: NA; Voltage: NA; Wattage: NA; Weight: NA; Datasheet: Y:\MIS_DATABASE\DATASHEETS\CONNECTORS\SFC-TH-SER.PDF
L3 = INDUCTOR: IND POWER 1uH 8A 20% SMD; Chkd/date: VASANTHA/050117; Crtd /date: CHAITHANYA/290312; Custom_Duty: 24%; Customs_HS_Code: 85437099; Distributor_name: MOUSER; Distributor_part_number: 994-XFL4020-102MEC; Footprint Path: Y:\MIS_DATABASE\Library\ALTIUM_TOOL\PCB_FOOTPRINTS\Altium_Footprint_Lib.PcbLib; Height: 2.10MM; Library Path: Y:\MIS_DATABASE\Library\ALTIUM_TOOL\SCHEMATICS_PARTS\MS_DISCRETE_Library.schlib; Mfr_name: COILCRAFT; Mfr_part_number: XFL4020-102MEC; Mistral Part No: 130012030053-R; Package: SMD; Project: IRIS; RoHS: RoHS; Temperature: -40°C+125°C; Tolerance: 20%; Voltage: NA; Wattage: NA; Weight: 169mg; Datasheet: Y:\MIS_DATABASE\DATASHEETS\DISCRETES\INDUCTORS\XFL4020.PDF
R213 R229 = RESISTOR: RES 0E 1/4W JUMPER 1206; Chkd/date: MANIRAJA/310818; Crtd /date: MANIRAJA/310818; Custom_Duty: 15%; Customs_HS_Code: 85332119; Distributor_name: DIGIKEY; Distributor_part_number: AF1206JR-070RL-ND; Footprint Path: Y:\MIS_DATABASE\Library\ALTIUM_TOOL\PCB_FOOTPRINTS\Altium_Footprint_Lib.PcbLib; Height: 0.65MM; Library Path: Y:\MIS_DATABASE\Library\ALTIUM_TOOL\SCHEMATICS_PARTS\MS_DISCRETE_Library.schlib; Mfr_name: YAGEO AMERICA; Mfr_part_number: AF1206JR-070RL; Mistral Part No: 110010030045-R; Package: 1206; Part_type: RESISTORS\FIXED; Project: TI_MAXIE_CPB; RoHS: RoHS; Temperature: -55°C+155°C; Tolerance: NA; Voltage: NA; Wattage: 1/4W; Weight: 30mg; Datasheet: Y:\MIS_DATABASE\DATASHEETS\RESISTORS\YA_AF-SER.PDF
R212 R214 R215 R217 R218 R221 R247 R255 R299-R302 = RESISTOR: RES 10K 1/16W 1% 0402; Chkd/date: VASANTHA/201216; Crtd /date: GEETHA/290506; Custom_Duty: 15%; Customs_HS_Code: 85332119; Distributor_name: DIGIKEY; Distributor_part_number: 311-10.0KLRTR-ND; Footprint Path: Y:\MIS_DATABASE\Library\ALTIUM_TOOL\PCB_FOOTPRINTS\Altium_Footprint_Lib.PcbLib; Height: 0.40MM; Library Path: Y:\MIS_DATABASE\Library\ALTIUM_TOOL\SCHEMATICS_PARTS\MS_DISCRETE_Library.schlib; Mfr_name: YAGEO AMERICA; Mfr_part_number: RC0402FR-0710KL; Mistral Part No: 110009030220-P; Package: 0402; Part_type: RESISTORS\FIXED; Project: VOCERA; RoHS: Pb-Free; Temperature: -55°C+155°C; Tolerance: 1%; Voltage: NA; Wattage: 1/16W; Weight: 0.65mg; Datasheet: Y:\MIS_DATABASE\DATASHEETS\RESISTORS\YAGEO-RC0402.PDF
R216 R233 R234 R240 R241 R243 R245 R246 R248 R251 R252 R298 R305 R306 R308 R311 = RESISTOR: RES 0E 1/16W 0402; Chkd/date: VASANTHA/201216; Crtd /date: MUDDU/190810; Custom_Duty: 15%; Customs_HS_Code: 85332119; Distributor_name: DIGIKEY; Distributor_part_number: 541-0.0JCT-ND; Footprint Path: Y:\MIS_DATABASE\Library\ALTIUM_TOOL\PCB_FOOTPRINTS\Altium_Footprint_Lib.PcbLib; Height: 0.40MM; Library Path: Y:\MIS_DATABASE\Library\ALTIUM_TOOL\SCHEMATICS_PARTS\MS_DISCRETE_Library.schlib; Mfr_name: VISHAY; Mfr_part_number: CRCW04020000Z0ED; Mistral Part No: 110010080019-P; Package: 0402; Part_type: RESISTORS\FIXED; Project: PB_BUGBASE; RoHS: Pb-Free; Temperature: -55°C+155°C; Tolerance: NA; Voltage: NA; Wattage: 1/16W; Weight: 0.65g/1000pcs; Datasheet: Y:\MIS_DATABASE\DATASHEETS\RESISTORS\CRCW0603.PDF
R219 = RESISTOR: RES 100K 1/16W 5% 0402; Chkd/date: VASANTHA/061216; Crtd /date: BAVISH/010611; Custom_Duty: 15%; Customs_HS_Code: 85332119; Distributor_name: DIGIKEY; Distributor_part_number: 541-100KJCT-ND; Height: 0.40MM; Mfr_name: VISHAY; Mfr_part_number: CRCW0402100KJNED; Mistral Part No: 110011060002-R; Package: 0402; Part_type: RESISTORS\FIXED; Project: AM4515_EVM_LCD; RoHS: RoHS; Temperature: -55°C+155°C; Tolerance: 5%; Voltage: NA; Wattage: 1/16W; Weight: 0.65mg; Datasheet: Y:\MIS_DATABASE\DATASHEETS\RESISTORS\CRCW0603.PDF
R220 = RESISTOR: RES 1.96K 1/10W 1% 0402; Chkd/date: JEBRAN/260315; Crtd /date: USMAN/121012; Custom_Duty: 15%; Customs_HS_Code: 85332119; Distributor_name: DIGIKEY; Distributor_part_number: P1.96KLCT-ND; Height: 0.40MM; Mfr_name: PANASONIC; Mfr_part_number: ERJ-2RKF1961X; Mistral Part No: 110012100019-R; Package: 0402; Part_type: RESISTORS\FIXED; Project: ITS-CONTROLER_CARD; Remarks: WATTAGE CHANGED; RoHS: RoHS; Temperature: -55°C+125°C; Tolerance: 1%; Voltage: NA; Wattage: 1/10W; Weight: NA; Datasheet: Y:\MIS_DATABASE\DATASHEETS\RESISTORS\PAN-ERJSERIES.PDF
R222 = RESISTOR: RES 2.2K 1/16W 5% 0402; Chkd/date: VASANTHA/061216; Crtd /date: BAVISH/021210; Custom_Duty: 15%; Customs_HS_Code: 85332119; Distributor_name: DIGIKEY; Distributor_part_number: 311-2.2KJRCT-ND; Footprint Path: VALUE IS VAILABLE 3 TIMES; Height: 0.40MM; Mfr_name: YAGEO AMERICA; Mfr_part_number: RC0402JR-072K2L; Mistral Part No: 110010120018-R; Package: 0402; Part_type: RESISTORS\FIXED; Project: TE4; RoHS: RoHS; Temperature: -55°C+155°C; Tolerance: 5%; Voltage: NA; Wattage: 1/16W; Weight: 0.65mg; Datasheet: Y:\MIS_DATABASE\DATASHEETS\RESISTORS\YAGEO.PDF
R223 = RESISTOR: RES 34K 1/10W 1% 0402; Chkd/date: NAVEED/280515; Crtd /date: NAVEED/280515; Custom_Duty: 15%; Customs_HS_Code: 85332119; Distributor_name: DIGIKEY; Distributor_part_number: P34.0KLCT-ND; Height: 0.40MM; Mfr_name: PANASONIC-ECG; Mfr_part_number: ERJ-2RKF3402X; Mistral Part No: 110015050011-R; Package: 0402; Part_type: RESISTORS\FIXED; Project: DLRL NARROW BAND; RoHS: RoHS; Temperature: -55°C+155°C; Tolerance: 1%; Voltage: NA; Wattage: 1/10W; Weight: NA; Datasheet: Y:\MIS_DATABASE\DATASHEETS\RESISTORS\PAN-ERJSERIES.PDF
TP22-TP27 = TESTPOINT: TESTPOINT CIR 40 SMD; Chkd/date: MAZHAR/190505; Crtd /date: MAZHAR/190505; Distributor_name: NA; Distributor_part_number: NA; Footprint Path: Y:\MIS_DATABASE\Library\ALTIUM_TOOL\PCB_FOOTPRINTS\Altium_Footprint_Lib.PcbLib; Height: NA; Library Path: Y:\MIS_DATABASE\Library\ALTIUM_TOOL\SCHEMATICS_PARTS\MS_DISCRETE_Library.schlib; MECHANICAL 3D STEP FILE: NA; Mfr_name: LOCAL; Mistral Part No: 130009030933; Package: SMD; Project: RAINIER-3; RoHS: NA; Temperature: NA; Tolerance: NA; Voltage: NA; Wattage: NA; Weight: NA; Datasheet: NA
U22 = TPS54620_QFN14: IC REG BUCK SYNC ADJ 8A QFN14; Chkd/date: NAVEED/280715; Crtd /date: NAVEED/080714; Custom_Duty: 15%; Customs_HS_Code: 85423100; Distributor_name: DIGIKEY; Distributor_part_number: 296-29744-2-ND; Height: 1.00MM; Mfr_name: TEXAS INSTRUMENTS; Mistral Part No: 142014040004-R; Package: QFN14; Part_type: ICS\POWER\CONVERTER; Project: DC_MIST_RF_TEST CARD; RoHS: RoHS; Temperature: -40°C+150°C; Tolerance: NA; Voltage: NA; Wattage: NA; Weight: NA; Datasheet: Y:\MIS_DATABASE\DATASHEETS\ICS\POWER\TPS54821.PDF
U24 = SN74LVC1G08DBVRE4_SOT23-5: IC SINGLE 2-INPUT POSITIVE AND GATE SOT23-5; Chkd/date: SUHAS/221010; Crtd /date: USMAN/151008; Custom_Duty: 15%; Customs_HS_Code: 85423100; Distributor_name: DIGIKEY; Distributor_part_number: SN74LVC1G08DBVRE4-ND; Height: 1.45MM; Mfr_name: TEXAS INSTRUMENTS; Mistral Part No: 141009060026-R; Part_type: ICS\DIGITAL\GATES; Project: KHAN_MAIN; RoHS: Sb/ Br FREE; Temperature: -40°C+85°C; Datasheet: Y:\MIS_DATABASE\DATASHEETS\ICS\DIGITAL\GATES\SN74LVC1G08.PDF
C127 = CAP: CAP CERAMIC 1000pF 2KV 10% X7R 1206; Chkd/date: SHREESHAIL/291106; Crtd /date: MAZHAR/281106; Custom_Duty: 15%; Customs_HS_Code: 85322990; Distributor_name: DIGIKEY; Distributor_part_number: 478-2956-1-ND; Footprint Path: Y:\MIS_DATABASE\Library\ALTIUM_TOOL\PCB_FOOTPRINTS\Altium_Footprint_Lib.PcbLib; Height: 1.50MM; Library Path: Y:\MIS_DATABASE\Library\ALTIUM_TOOL\SCHEMATICS_PARTS\MS_DISCRETE_Library.schlib; Mfr_name: AVX CORPORATION; Mfr_part_number: 1206GC102KAT1A; Mistral Part No: 120009030147-R; Package: 1206; Part_type: CAPACITORS\CERAMIC; Project: ADR1B; RoHS: RoHS; Temperature: -55°C+125°C; Tolerance: 10%; Voltage: 2KV; Weight: NA; Datasheet: Y:\MIS_DATABASE\DATASHEETS\CAPACITORS\AVX_MLC.PDF
C128 C138 C139 C158 C229 = CAP: CAP CERAMIC 4.7uF 16V 20% X5R 0402; Chkd/date: MANIRAJA/171017; Crtd /date: MANIRAJA/171017; Custom_Duty: 15%; Customs_HS_Code: 85322990; Distributor_name: DIGIKEY; Distributor_part_number: 478-10788-1-ND; Height: 0.71MM; Mfr_name: AVX CORPORATION; Mfr_part_number: 0402YD475MAT2A; Mistral Part No: 120017100010-R; Package: 0402; Part_type: CAPACITORS\CERAMIC; Project: TI_MAXIE_CPB; RoHS: RoHS; Temperature: -55°C+85°C; Tolerance: 20%; Voltage: 16V; Wattage: NA; Weight: NA; Datasheet: Y:\MIS_DATABASE\DATASHEETS\CAPACITORS\AVX_MLC.PDF
C129 = CAP_POL: CAP TANTALUM 150uF 10V 10% ESR 0.9E D7373; Chkd/date: MANIRAJA/240118; Crtd /date: MANIRAJA/240118; Custom_Duty: 15%; Customs_HS_Code: 85322990; Distributor_name: DIGIKEY; Distributor_part_number: 478-11241-1-ND; Height: 3.10MM; Mfr_name: AVX CORPORATION; Mfr_part_number: TAJD157K010TNJV; Mistral Part No: 120018010025-R; Package: D7373; Part_type: CAPACITORS\TANTALUM; Project: TI_MAXIE_CPB; RoHS: RoHS; Temperature: -55°C+125°C; Tolerance: 10%; Voltage: 10V; Wattage: NA; Weight: NA; Datasheet: Y:\MIS_DATABASE\DATASHEETS\CAPACITORS\TAJD156.PDF
FL16 = EMI_FILTER: PASSIVE FILTER EMI 4.7uF 0805-3; Chkd/date: VASANTHA/191216; Crtd /date: USMAN/200409; Custom_Duty: 24%; Customs_HS_Code: 85437099; Distributor_name: NA; Distributor_part_number: NA; Height: 0.95MM; Mfr_name: MURATA; Mfr_part_number: NFM21PC475B1A3; Mistral Part No: 130009060011; Package: 0805; Part_type: MISC\FILTER; Project: AXON; Temperature: -40°C+85°C; Tolerance: NA; Voltage: NA; Wattage: NA; Weight: NA; Datasheet: Y:\MIS_DATABASE\DATASHEETS\DISCRETES\INDUCTORS\NFM21P.PDF
FL25 = EMIFILTER_ACM: PASSIVE FILTER COMMON MODE 90E 400mA SMD; Chkd/date: MAZHAR/040809; Crtd /date: MAZHAR/270907; Custom_Duty: 24%; Customs_HS_Code: 85437099; Distributor_name: DIGIKEY; Distributor_part_number: 445-2207-2-ND; Height: 1.30MM; Mfr_name: TDK CORPORATION; Mfr_part_number: ACM2012-900-2P; Mistral Part No: 130009030803-R; Package: SMD; Part_type: MISC\FILTER; Project: SMART VIEW_NVR; RoHS: RoHS; Datasheet: Y:\MIS_DATABASE\DATASHEETS\ICS\MISC\ACM2012-SER.PDF
J5 = HEADER_3X2: CON HDR 2X3 2.54MM PITCH ST TH; Chkd/date: MANIRAJA/230118; Crtd /date: MANIRAJA/220118; Custom_Duty: 24%; Customs_HS_Code: 85369090; Distributor_name: DIGIKEY; Distributor_part_number: SAM1034-03-ND; Height: 8.38MM; Mfr_name: SAMTEC; Mfr_part_number: TSW-103-07-T-D; Mistral Part No: 150018010019-R; Package: THRU-HOLE; Part_type: CONNECTOR\HEADERS; Project: TI_MAXIE_CPB; RoHS: RoHS; TEXT: HOST; Temperature: -55°C+105°C; Tolerance: NA; Voltage: NA; Wattage: NA; Weight: NA; Datasheet: Y:\MIS_DATABASE\DATASHEETS\CONNECTORS\TSW-MK.PDF
J13 = CON_USB_MINI-AB_10: CON MICRO USB-AB TYPE 5POS FEMALE RT SMD; Chkd/date: VASANTHA/060117; Crtd /date: MAZHAR/290909; Custom_Duty: 24%; Customs_HS_Code: 85369090; Distributor_name: DIGIKEY; Distributor_part_number: WM17144CT-ND; Height: 3.10MM; Mfr_name: MOLEX; Mfr_part_number: 475900001; Mistral Part No: 150009090024-R; Package: SMD; Part_type: CONNECTOR\USB; Project: GOLDEN-I; RoHS: NA; TEXT: USB 2.0; Temperature: -30°C+85°C; Tolerance: NA; Voltage: NA; Wattage: NA; Weight: NA; Datasheet: Y:\MIS_DATABASE\DATASHEETS\CONNECTORS\475900.PDF
R211 R254 = RESISTOR: RES 1M 1/16W 1% 0402; Chkd/date: VASANTHA/200614; Crtd /date: NAVEED/170614; Custom_Duty: 15%; Customs_HS_Code: 85332119; Distributor_name: DIGIKEY; Distributor_part_number: RMCF0402FT1M00CT-ND; Footprint Path: Y:\MIS_DATABASE\Library\ALTIUM_TOOL\PCB_FOOTPRINTS\Altium_Footprint_Lib.PcbLib; Height: 0.40MM; Library Path: Y:\MIS_DATABASE\Library\ALTIUM_TOOL\SCHEMATICS_PARTS\MS_DISCRETE_Library.schlib; Mfr_name: STACKPOLE ELECTRONICS; Mfr_part_number: RMCF0402FT1M00; Mistral Part No: 110014060045-R; Package: 0402; Part_type: RESISTORS\FIXED; Project: AEGIS_POM; RoHS: RoHS; Temperature: -55°C+155°C; Tolerance: 1%; Voltage: NA; Wattage: 1/16W; Weight: 0.57mg; Datasheet: Y:\MIS_DATABASE\DATASHEETS\RESISTORS\RMCF-SERIES1.PDF
U20 = TPD4S012DRY_SON6: IC 4CH ESD SOLUTION SON6; Chkd/date: VASANTHA/060117; Crtd /date: BAVISH/190811; Custom_Duty: 15%; Customs_HS_Code: 85423100; Distributor_name: DIGIKEY; Distributor_part_number: 296-24244-1-ND; Height: 0.60MM; Mfr_name: TEXAS INSTRUMENTS; Mistral Part No: 141011080022-R; Package: SON6; Part_type: ICS\INTERFACE; Project: ACRO_DM3730; RoHS: RoHS; Temperature: -40°C+85°C; Tolerance: NA; Voltage: NA; Wattage: NA; Weight: NA; Datasheet: Y:\MIS_DATABASE\DATASHEETS\ICS\INTERFACE\TPD4S012.PDF
U21 = TPS2051BD_SOIC8: IC POWER DISTRIBUTION SWITCH SOIC8; Chkd/date: NAVEED/150714; Crtd /date: VASANTHA/190614; Custom_Duty: 15%; Customs_HS_Code: 85423100; Distributor_name: DIGIKEY; Distributor_part_number: 296-26911-5-ND; Footprint Path: Y:\MIS_DATABASE\Library\ALTIUM_TOOL\PCB_FOOTPRINTS\Altium_Footprint_Lib.PcbLib; Height: 1.75MM; Library Path: Y:\MIS_DATABASE\Library\ALTIUM_TOOL\SCHEMATICS_PARTS\MS_MISCPOWER_Library.schlib; Mfr_name: TEXAS INSTRUMENTS; Mistral Part No: 142014060011-R; Package: SOIC8; Part_type: ICS\POWER; Project: AEGIS_POM; RoHS: RoHS; Temperature: -40°C+125°C; Tolerance: NA; Voltage: NA; Wattage: NA; Weight: 72.6mg; Datasheet: Y:\MIS_DATABASE\DATASHEETS\MISC\REGULATORS\TPS2051BDBVR.PDF
U25 = CAT24C256WI-GT3_SOIC8: IC 256K I2C CMOS SERIAL EEPROM SOIC8; Chkd/date: MANIRAJA/130617; Crtd /date: MUDDU/270510; Custom_Duty: 15%; Customs_HS_Code: 85423100; Distributor_name: DIGIKEY; Distributor_part_number: CAT24C256WI-GT3-ND; Height: 1.75MM; Mfr_name: ON SEMICONDUCTOR; Mistral Part No: 141110050004-R; Package: SOIC8; Part_type: ICS\DIGITAL\MEMORY; Project: CENTAURUS; RoHS: RoHS; Temperature: -40°C+85°C; Tolerance: NA; Voltage: NA; Wattage: NA; Weight: 540mg; Datasheet: Y:\MIS_DATABASE\DATASHEETS\ICS\MEMORY\CAT24C256WI.PDF
C156 C157 = CAP: CAP CERAMIC 27pF 50V 5% NP0 0402; Chkd/date: MAZHAR/241208; Crtd /date: GEETHA/090606; Custom_Duty: 15%; Customs_HS_Code: 85322990; Distributor_name: DIGIKEY; Distributor_part_number: 311-1019-1-ND; Height: 0.55MM; Mfr_name: YAGEO AMERICA; Mfr_part_number: CC0402JRNPO9BN270; Mistral Part No: 120009030351; Package: 0402; Part_type: CAPACITORS\CERAMIC; Project: PNAV; Tolerance: 5%; Voltage: 50V; Datasheet: Y:\MIS_DATABASE\DATASHEETS\CAPACITORS\YACC0603.PDF
C159 C221 C222 C227 = CAP: CAP CERAMIC 0.47uF 10V 10% X7S AUTO 0402; Chkd/date: MANIRAJA/190220; Crtd /date: ALVY/190220; Custom_Duty: 15%; Customs_HS_Code: 85322990; Distributor_name: DIGIKEY; Distributor_part_number: 445-16100-1-ND; Footprint Path: Y:\MIS_DATABASE\Library\ALTIUM_TOOL\PCB_FOOTPRINTS\Altium_Footprint_Lib.PcbLib; Height: 0.55MM; Library Path: Y:\MIS_DATABASE\Library\ALTIUM_TOOL\SCHEMATICS_PARTS\MS_DISCRETE_Library.schlib; Mfr_name: TDK CORPORATION; Mfr_part_number: CGA2B3X7S1A474K050BB; Mistral Part No: 120018090057-R; Package: 0402; Part_type: CAPACITORS\CERAMIC; Project: TI_MAXIE_CPB; RoHS: RoHS; Temperature: -55°C+125°C; Tolerance: 10%; Voltage: 10V; Wattage: NA; Weight: 0.65mg; Datasheet: Y:\MIS_DATABASE\DATASHEETS\CAPACITORS\CGA2B3X7S1A474K050BB.PDF
C223 C224 = CAP: CAP CERAMIC 0.1uF 25V 10% X5R 0402; Chkd/date: MANIRAJA/190220; Crtd /date: ALVY/190220; Custom_Duty: 15%; Customs_HS_Code: 85322990; Distributor_name: DIGIKEY; Distributor_part_number: 311-1697-1-ND; Footprint Path: Y:\MIS_DATABASE\Library\ALTIUM_TOOL\PCB_FOOTPRINTS\Altium_Footprint_Lib.PcbLib; Height: 0.55MM; Library Path: Y:\MIS_DATABASE\Library\ALTIUM_TOOL\SCHEMATICS_PARTS\MS_DISCRETE_Library.schlib; Mfr_name: YAGEO AMERICA; Mfr_part_number: CC0402KRX5R8BB104; Mistral Part No: 120017080016-R; Package: 0402; Part_type: CAPACITORS\CERAMIC; Project: TI_MAXIE_CPB; RoHS: RoHS; SIGNAL_MODEL: cap; Temperature: -55°C+85°C; Tolerance: 10%; Voltage: 25V; Wattage: NA; Weight: 0.65mg; Datasheet: Y:\MIS_DATABASE\DATASHEETS\CAPACITORS\YACC-X5R.PDF
C230 = CAP: CAP CERAMIC 1uF 10V 10% X5R 0402; Chkd/date: BALACHANDAR/160514; Crtd /date: SARANYA/060514; Custom_Duty: 15%; Customs_HS_Code: 85322990; Distributor_name: DIGIKEY; Distributor_part_number: 478-4596-1-ND; Height: 0.56MM; Mfr_name: AVX CORPORATION; Mfr_part_number: 0402ZD105KAT2A; Mistral Part No: 120014050010-R; Package: 0402; Part_type: CAPACITORS\CERAMIC; Project: AEGIS GP BETA2; RoHS: RoHS; Temperature: -55°C+85°C; Tolerance: 10%; Voltage: 10V; Wattage: NA; Weight: NA; Datasheet: Y:\MIS_DATABASE\DATASHEETS\CAPACITORS\AVX_MLC.PDF
FL17-FL20 = CAP_FILTER: PASSIVE FILTER EMI 0.47uF 0805; Chkd/date: RAGESH/121010; Crtd /date: MUDDU/010210; Custom_Duty: 24%; Customs_HS_Code: 85437099; Distributor_name: DIGIKEY; Distributor_part_number: 490-2537-1-ND; Height: 0.95MM; Mfr_name: MURATA; Mfr_part_number: NFM21PC474R1C3D; Mistral Part No: 130010010009; Package: 0805; Part_type: MISC\FILTER; Project: KOPIN_MODULS; Temperature: -55°C+125°C; Weight: NA; Datasheet: Y:\MIS_DATABASE\DATASHEETS\ICS\MISC\NFM21P.PDF
R224 R225 R237 R244 = RESISTOR: RES 49.9E 1/16W 1% 0402; Chkd/date: VASANTHA/201216; Crtd /date: MAZHAR/201005; Custom_Duty: 15%; Customs_HS_Code: 85332119; Distributor_name: DIGIKEY; Distributor_part_number: P49.9LCT-ND; Footprint Path: Y:\MIS_DATABASE\Library\ALTIUM_TOOL\PCB_FOOTPRINTS\Altium_Footprint_Lib.PcbLib; Height: 0.40MM; Library Path: Y:\MIS_DATABASE\Library\ALTIUM_TOOL\SCHEMATICS_PARTS\MS_DISCRETE_Library.schlib; Mfr_name: PANASONIC-ECG; Mfr_part_number: ERJ-2RKF49R9X; Mistral Part No: 110009030897-R; Package: 0402; Part_type: RESISTORS\FIXED; Project: RED EYE; RoHS: RoHS; Temperature: -55°C+125°C; Tolerance: 1%; Voltage: NA; Wattage: 1/16W; Weight: 0.8g/1000pcs; Datasheet: Y:\MIS_DATABASE\DATASHEETS\RESISTORS\ERJ-1G.PDF
R226 R227 R238 R242 = RESISTOR: RES 33E 1/16W 1% 0402; Chkd/date: VASANTHA/061216; Crtd /date: JEBRAN/171114; Custom_Duty: 15%; Customs_HS_Code: 85332119; Distributor_name: DIGIKEY; Distributor_part_number: P33.0LCT-ND; Height: 0.40MM; Mfr_name: PANASONIC-ECG; Mfr_part_number: ERJ-2RKF33R0X; Mistral Part No: 110014110006-R; Package: 0402; Part_type: RESISTORS\FIXED; Project: ZK BIOMETRIC; RoHS: RoHS; Temperature: -55°C+125°C; Tolerance: 1%; Voltage: NA; Wattage: 1/16W; Weight: 0.8g/1000pcs; Datasheet: Y:\MIS_DATABASE\DATASHEETS\RESISTORS\PAN-ERJSERIES.PDF
R228 R230-R232 R235 R236 R239 R253 R297 R307 = RESISTOR: RES 4.7K 1/16W 5% 0402; Chkd/date: VASANTHA/130516; Crtd /date: VASANTHA/130516; Custom_Duty: 15%; Customs_HS_Code: 85332119; Distributor_name: DIGIKEY; Distributor_part_number: 311-4.7KJRCT-ND; Height: 0.55MM; Mfr_name: YAGEO AMERICA; Mfr_part_number: RC0402JR-074K7L; Mistral Part No: 110009030792-R; Package: 0402; Part_type: RESISTORS\FIXED; Project: TMDXCSK368; RoHS: RoHS; Temperature: -55°C+155°C; Tolerance: 5%; Voltage: NA; Wattage: 1/16W; Weight: NA; Datasheet: Y:\MIS_DATABASE\DATASHEETS\RESISTORS\YAGEO-RC0402.PDF
R250 R304 = RESISTOR: RES 1K 1/16W 5% 0402; Chkd/date: VASANTHA/201216; Crtd /date: MAZHAR/230805; Custom_Duty: 15%; Customs_HS_Code: 85332119; Distributor_name: DIGIKEY; Distributor_part_number: P1.0KJCT-ND; Footprint Path: Y:\MIS_DATABASE\Library\ALTIUM_TOOL\PCB_FOOTPRINTS\Altium_Footprint_Lib.PcbLib; Height: 0.40MM; Library Path: Y:\MIS_DATABASE\Library\ALTIUM_TOOL\SCHEMATICS_PARTS\MS_DISCRETE_Library.schlib; Mfr_name: PANASONIC-ECG; Mfr_part_number: ERJ-2GEJ102X; Mistral Part No: 110009030400-R; Package: 0402; Part_type: RESISTORS\FIXED; Project: HSE; RoHS: RoHS; Temperature: -55°C+125°C; Tolerance: 5%; Voltage: NA; Wattage: 1/16W; Weight: 0.8g/1000pcs; Datasheet: Y:\MIS_DATABASE\DATASHEETS\RESISTORS\ERJ12.PDF
U23 = CDCI6214RGET_VQFN24: IC PCIE GEN4 CLOCK GENERATOR WITH PROGRAMMABLE O/P AND EEPROM VQFN24; Chkd/date: MANIRAJA/051017; Crtd /date: MANIRAJA/051017; Custom_Duty: 15%; Customs_HS_Code: 85423100; Distributor_name: NA; Distributor_part_number: NA; Height: 1.00MM; Mfr_name: TEXAS INSTRUMENTS; Mistral Part No: 141017100002-R; Package: VQFN24; Part_type: ICS\DIGITAL\PERIPHERAL; Project: TI_SVB_MAXWELL_DUT; RoHS: RoHS; Temperature: -40°C+85°C; Tolerance: NA; Voltage: NA; Wattage: NA; Weight: NA; Datasheet: Y:\MIS_DATABASE\DATASHEETS\ICS\DIGITAL\PERIPHERAL\CDCI6214.PDF
Y6 = CRY_CX3225GB: CRY 25.000MHZ 8PF SMD; Chkd/date: NAVEED/070115; Crtd /date: VASANTHA/111114; Custom_Duty: 24%; Customs_HS_Code: 85439000; Distributor_name: DIGIKEY; Distributor_part_number: 1253-1353-1-ND; Height: 0.90MM; Mfr_name: KYOCERA; Mfr_part_number: CX3225SB25000D0FFFCC; Mistral Part No: 130014110014-R; Package: SMD; Part_type: CRYSTAL; Project: GALILEO_EVM; RoHS: RoHS; Temperature: -40°C+85°C; Tolerance: NA; Voltage: NA; Wattage: NA; Weight: NA; Datasheet: Y:\MIS_DATABASE\DATASHEETS\MISC\CRY_OSC\CX3225SB.PDF
ACC1 = ACCESSORY: ACCESSORIE CONNECTOR SHUNT 2X3 POS EDGE MOUNT SOCKET STRIP; Chkd/date: MANIRAJA/141117; Crtd /date: MANIRAJA/141117; Distributor_name: DIGIKEY; Distributor_part_number: SAM10620-ND; Mfr_name: SAMTEC; Mistral Part No: 160017110050-R; Part_type: ACCESSORIES; Project: TI_MAXIE_CPB; RoHS: RoHS; Temperature: -55°C+125°C; Datasheet: Y:\MIS_DATABASE\DATASHEETS\MISC\ACCESSORIES\SAMTEC-MNT-SER.PDF
ACC2 = ACCESSORY: ACCESSORIE JUMPER SHORTING GOLD FLASH; Chkd/date: SUHAS\211010; Crtd /date: USMAN/301208; Distributor_name: DIGIKEY; Distributor_part_number: S9001-ND; Mfr_name: SULLINS CONNECTOR; Mistral Part No: 160009030153-R; Part_type: MISC\ACCESSORIES; Project: SMART VIEW_NVR; RoHS: RoHS; Datasheet: Y:\MIS_DATABASE\DATASHEETS\MISC\MODULES\SPC02SYAN.PDF
ACC3-ACC9 = WASHER_PLAIN: PLAIN WASHER FOR M3 SS-316; Chkd/date: MANIRAJA/190218; Crtd /date: MANIRAJA/190218; Distributor_name: DIGIKEY; Distributor_part_number: 36-4692-ND; Footprint Path: Y:\MIS_DATABASE\Library\ALTIUM_TOOL\PCB_FOOTPRINTS\Altium_Footprint_Lib.PcbLib; Library Path: Y:\MIS_DATABASE\Library\ALTIUM_TOOL\SCHEMATICS_PARTS\MS_MECHANICAL_Library.schlib; Mfr_name: KEYSTONE; Mfr_part_number: 4692; Mistral Part No: 160018020078-R; Package: SS; Part_type: MECHANICAL\WASHERS; Project: TI_MAXIE_CPB; RoHS: RoHS; Datasheet: Y:\MIS_DATABASE\DATASHEETS\MISC\MECHANICAL\4692.PDF
FID1-FID6 = Fiducial
LBL1 LBL2 = ACCESSORY_THT-3-423-10: ACCESSORIE 1 WORKHORSE POLYSTER LABLE 0.25" X 1"; Chkd/date: MANIRAJA/270218; Crtd /date: ALVY/260218; Footprint Path: Y:\MIS_DATABASE\Library\ALTIUM_TOOL\PCB_FOOTPRINTS\Altium_Footprint_Lib.PcbLib; Library Path: Y:\MIS_DATABASE\Library\ALTIUM_TOOL\SCHEMATICS_PARTS\MS_MECHANICAL_Library.schlib; Mfr_name: BRADY; Mistral Part No: 160018020185; Part_type: ACCESSORIES; Project: TI_MAXIE_CPB
Logo1 Logo3 Logo4 = TI_Logo
Logo2 = FCC_disclaimer
MH1-MH5 = SCREW_PAN: PHILLIPS PAN HEAD SCREW - M2.5 X 4 SS-316; Chkd/date: MANIRAJA/190218; Crtd /date: MANIRAJA/190218; Distributor_name: DIGIKEY; Distributor_part_number: 36-29300-ND; Footprint Path: Y:\MIS_DATABASE\Library\ALTIUM_TOOL\PCB_FOOTPRINTS\Altium_Footprint_Lib.PcbLib; Height: 4.00MM; Library Path: Y:\MIS_DATABASE\Library\ALTIUM_TOOL\SCHEMATICS_PARTS\MS_MECHANICAL_Library.schlib; Mfr_name: KEYSTONE; Mfr_part_number: 29300; Mistral Part No: 160018020076-R; Package: SS; Part_type: MECHANICAL\SCREWS; Project: TI_MAXIE_CPB; RoHS: RoHS; Datasheet: Y:\MIS_DATABASE\DATASHEETS\MISC\MECHANICAL\29300.PDF
PCB1 = ACCESSORY_PROC064: ACCESSORIE AM6x PCIE-2 LANE SERDES CARD; Chkd/date: MANIRAJA/230718; Crtd /date: MANIRAJA/230718; Mfr_name: TEXAS INSTRUMENTS; Mfr_part_number: PROC067; Mistral Part No: FY180646000803; Part_type: ACCESSORIES; Project: TI_MAXIE_CPB

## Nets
DGND4: C127.1 C128.2 C129.2 C130.2 C131.2 C132.2 C133.2 C134.2 C135.2 C136.2 C137.2 C138.2 C139.2 C140.2 C143.2 C144.2 C145.1 C146.1 C147.2 C148.2 C149.2 C150.2 C151.2 C152.2 C153.1 C154.1 C155.2 C156.1 C157.1 C158.2 C159.2 C160.2 C221.2 C222.2 C225.2 C226.2 C227.2 C228.2 C229.2 C230.1 C231.2 FL16.2(GND) FL17.2(GND1) FL18.2(GND1) FL19.2(GND1) FL20.2(GND1) J5.5 J13.5(GND) J15.A4(GND) J15.A12(GND) J15.A15(GND) J15.A18(GND) J15.A20(GND) J15.A23(GND) J15.A24(GND) J15.A27(GND) J15.A28(GND) J15.A31(GND) J15.B4(GND) J15.B7(GND) J15.B13(GND) J15.B16(GND) J15.B18(GND) J15.B21(GND) J15.B22(GND) J15.B25(GND) J15.B26(GND) J15.B29(GND) J15.B32(GND) J22.1(G) J22.4(G) J22.7(G) J22.10(G) J22.13(G) J22.17(G) J22.20(G) J22.23(G) J22.26(G) J22.29(G) J22.32(G) J22.35(G) J22.38(G) J22.41(G) J22.44(G) J22.48(G) J22.51(G) J22.54(G) J22.57(G) J22.60(G) J22.SH1 J22.SH2 J23.4 J23.5 J23.6 R211.1 R214.2 R222.2 R223.2 R224.2 R225.2 R228.2 R232.2 R237.2 R239.2 R243.1 R244.2 R253.2 R297.2 R304.2 R307.2 R308.2 U20.4(GND) U21.1(GND) U22.2(GND1) U22.3(GND2) U22.15(PAD) U23.25(GND) U24.3(GND) U25.4(VSS) Y6.2(NC1) Y6.4(NC2)
V3V3_REF_CDCI4: C154.2 C159.1 C229.1 FL19.3(OUT) U23.3(VDDREF)
V3V3_VCO_CDCI4: C153.2 C155.1 C158.1 C227.1 C230.2 FL20.3(OUT) U23.24(VDDVCO)
VDD12_CDCI4: C138.1 C145.2 C222.1 FL17.3(OUT) U23.16(VDDO12)
VDD34_CDCI4: C139.1 C146.2 C221.1 FL18.3(OUT) U23.15(VDDO34)
4_BOARDID_A0: J22.8(S5) R300.2 U25.1(A0)
4_BOARDID_A1: J22.9(S6) R301.2 U25.2(A1)
4_BOARDID_A2: J22.11(S7) R302.2 U25.3(A2)
4_BRD_DET: J22.45(E6) R308.1
4_CLKGEN_REFCLK1N: R237.1 R238.2 R240.2
4_CLKGEN_REFCLK1P: R241.2 R242.2 R244.1
4_CLKGEN_REFCLK2N: R225.1 R227.2 R251.2
4_CLKGEN_REFCLK2P: R224.1 R226.2 R252.2
4_EEPROM_WP: R255.2 U25.7(WP)
4_MCU_SCL: J15.B5(SMCLK) J22.2(S1) R234.1
4_MCU_SDA: J15.B6(SMDAT) J22.3(S2) R233.1
4_PCIe_CLKREQn: J15.B12(RSVD4) R217.2
4_PCIe_PRSNT1n: J15.A1(PRSNT1#) R216.2 R243.2 R298.2
4_PCIe_PRSNTA2n: J15.B17(PRSNT2#_1) J22.21(S11) R215.2 R216.1
4_PCIe_PRSNTB2n: J15.B31(PRSNT2#_2) J22.22(S12) R298.1 R299.2
4_PCIe_REFCLK_N: J15.A14(REFCLK-) R245.2 R251.1 R306.1
4_PCIe_REFCLK_P: J15.A13(REFCLK+) R246.2 R252.1 R305.1
4_PCIe_RESETn: J14.2 J15.A11(PERST#)
4_PCIe_RST: J22.6(S4) R247.1 U24.1(A)
4_PCIe_RXN0: J15.A17(PERn0) J22.40(S22)
4_PCIe_RXN1: J15.A22(PERn1) J22.52(S27)
4_PCIe_RXP0: J15.A16(PERp0) J22.39(S21)
4_PCIe_RXP1: J15.A21(PERp1) J22.53(S28)
4_PCIe_TCK: J15.A5(JTAG2) TP25.1(TP)
4_PCIe_TDI: J15.A6(JTAG3) TP24.1(TP)
4_PCIe_TDO: J15.A7(JTAG4) TP26.1(TP)
4_PCIe_TMS: J15.A8(JTAG5) TP23.1(TP)
4_PCIe_TRSTn: J15.B9(JTAG1) TP22.1(TP)
4_PCIe_TXN0: J15.B15(PETn0) J22.43(S24)
4_PCIe_TXN1: J15.B20(PETn1) J22.50(S26)
4_PCIe_TXP0: J15.B14(PETp0) J22.42(S23)
4_PCIe_TXP1: J15.B19(PETp1) J22.49(S25)
4_PCIe_WAKEn: J15.B11(WAKE#) R218.2 R311.2
4_PCIe_WAKEn_3V3: J22.46(E7) R311.1
4_PORz: J14.1 J22.12(S8)
4_PORz_OUT: J22.30(E4) R248.1 U24.2(B)
4_REFCLK_IN0N: J22.58(S31) R306.2
4_REFCLK_IN0P: J22.59(S32) R305.2
4_REFCLK_OUT0N: C224.2 J22.24(S13)
4_REFCLK_OUT0P: C223.2 J22.25(S14)
4_RESETn: J14.3 U24.4(Y)
4_USB_CM_DM: FL25.3 J13.2(D-) U20.3(ID)
4_USB_CM_DP: FL25.4 J13.3(D+) U20.2(D-)
4_USB_DM: FL25.2 J22.36(S19)
4_USB_DP: FL25.1 J22.37(S20)
4_USB_DRV_VBUS: J22.5(S3) R214.1 U21.4(EN)
4_USB_ID: J5.6 J13.4(ID) J22.14(E1) U20.1(D+)
4_USB_VBUS: C128.1 J5.1 J13.1(VCC) J22.47(E8) U20.6(VBUS) U21.6(OUT1) U21.7(OUT2) U21.8(OUT3)
4_VCC_1V8: C226.1 FL17.1(IN) FL18.1(IN) J23.3
4_VCC_3V3: C133.1 C137.1 C142.1 C151.1 L3.2 R213.1 R219.1 R221.2 R247.2 U24.5(VCC)
4_VCC_5V: C131.1 C231.1 FL16.1(I) J23.8 J23.10 R212.1
4_VCC_12V: C147.1 C150.1 C228.1 J23.7 J23.9 R229.1 U22.4(PVIN1) U22.5(PVIN2) U22.6(VIN)
4_VCC_FUN_3V3: C160.1 C225.1 FL19.1(IN) FL20.1(IN) J22.18(S9) J22.19(S10) R230.1 R231.1 R235.1 R236.1 R250.1 R255.1 R300.1 R301.1 R302.1 U25.8(VCC)
4_VCC_PCIE_3V3: C136.1 C148.1 J15.A9(+3.3V) J15.A10(+3.3V) J15.B8(+3.3V) J15.B10(3.3VAUX) R213.2 R215.1 R217.1 R218.1 R299.1
4_VCC_PCIE_12V: C132.1 C134.1 C135.1 C149.1 C152.1 J15.A2(+12V) J15.A3(+12V) J15.B1(+12V) J15.B2(+12V) J15.B3(+12V) R229.2
4_WKUP_SCL: J22.33(S17) U25.6(SCL)
4_WKUP_SDA: J22.34(S18) U25.5(SDA)
CDCI4_EEPROMSEL: R250.2 R304.1 U23.23(EEPROMSEL)
CDCI4_OE1: R235.2 R297.1 U23.20(STATUS/GPIO1)
CDCI4_OE2: R228.1 R231.2 R233.2 U23.19(SDA/GPIO2)
CDCI4_OE3: R230.2 R232.1 R234.2 U23.12(SCL/GPIO3)
CDCI4_OE4: R236.2 R239.1 U23.11(OE/GPIO4)
CDCI4_REFSEL: R307.1 U23.4(REFSEL)
CDCI4_RST: R248.2 R253.1 U23.8(RESETN/SYNC)
CDCI4_XIN: C156.2 R254.1 U23.1(XIN) Y6.3(HOT2)
CDCI4_XOUT: C157.2 R254.2 TP27.1(TP) U23.2(XOUT) U23.7(Y0) Y6.1(HOT1)
CDCI4_Y1N: R238.1 U23.21(Y1N)
CDCI4_Y1P: R242.1 U23.22(Y1P)
CDCI4_Y2N: R227.1 U23.17(Y2N)
CDCI4_Y2P: R226.1 U23.18(Y2P)
PWR_GOOD4: R219.2 U22.14(PWRGD)
USB_SHIELD4: C127.2 J13.6(SH1) J13.7(SH2) J13.8(SH3) J13.9(SH4) J13.10(SH5) R211.2
N16880317: C130.1 FL16.3(O) U21.2(IN1) U21.3(IN2)
N16880346: R212.2 U21.5(~{OC})
N17084018: C223.1 R241.1 R246.1
N17084031: C224.1 R240.1 R245.1
N17117472: C142.2 R221.1 R222.1 U22.7(VSENSE)
N17117476: C141.1 L3.1 U22.11(PH1) U22.12(PH2)
N17117528: C144.1 R220.2
N17117530: C143.1 R220.1 U22.8(COMP)
N17117540: R223.1 U22.1(RT/CLK)
N17117546: C140.1 U22.9(SS/TR)
N17117564: C141.2 U22.13(BOOT)
N17797147: C129.1 J5.2

Not connected (* = marked no-connect by the designer): J5 3* 4*; J15 A19(RSVD1)* A25(PERp2)* A26(PERn2)* A29(PERp3)* A30(PERn3)* A32(RSVD2)* B23(PETp2)* B24(PETn2)* B27(PETp3)* B28(PETn3)* B30(RSVD3)*; J22 15(E2)* 16(E3)* 27(S15)* 28(S16)* 31(E5)* 55(S29)* 56(S30)*; J23 1* 2*; U20 5(NC)*; U22 10(EN)*; U23 5(REFP)* 6(REFN)* 9(Y4N)* 10(Y4P)* 13(Y3N)* 14(Y3P)*

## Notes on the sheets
sheet 1
- HARDWARE SCHEMATICS
- SCREWS and WASHER's
- JUMPERs
- To be mounted on J5 for USB Host operation.
- To be mounted on J14 pin 3 and 2 for Host operation.
- These mechanicals will be used to secure this board to PROC062
- FIDUCIALS
- LOGOs
- Texas Intruments
- For Evaluation only; not FCC approved for resale
- WEEE Mark
- CE Mark
- ASSEMBLY NOTES
- 1. All MSL components should be baked as per JEDEC standard.
  2. PCB should be baked at 120 degree for 8 hours.
  3. Board assembly must comply with workmanship standards.
  IPC-A-610 Class 2, unless otherwise specified.
  4. These assemblies are ESD sensitive, ESD precautions
  shall be observed.
  5. These assemblies must be clean and free from flux and
  all contaminants. Use of no clean flux is not acceptable.
  6. Provide serial numbers to the assembled boards for identification.
  7. The assembled board are wrapped in ESD Covers(individual) and
  packed securely before shipment.
- LABEL
- BARE PCB
- Assembly Revision
- Board Serial No.
sheet 2
- MAXWELL SERDES PCIe x2 PERSONALITY CARD
- TABLE OF CONTENTS
- PAGE
- CONTENTS
- REV
- A
- 01
- TABLE OF CONTENTS
- VER
- 1.0
- 02
- REVISION HISTORY
- 03
- BLOCK DIAGRAM
- 04
- 2LANEPCIe_SERDES & PCIE CON
- 05
- 2LANEPCIE_USB2.0 &BRD_ID
- 06
- 2LANEPCIE_CLK
- 07
- HARDWARE SCHEMATICS
sheet 3
- REVISION HISTORY
- REV #
- VER #
- DATE
- DESCRIPTION OF CHANGES
- AUTHOR
- REVIEWED  BY
- APPROVED  BY
- A
- 0.1
- 31th JAN 2020
- Drafted from Rev E3, Ver 1.0 schematics.
- Mistral Design Team
- AJIT MB
- AJIT MB
- A
- 0.2
- 31th JAN 2020
- Made R247 as DNI
- Mistral Design Team
- AJIT MB
- AJIT MB
- A
- 0.3
- 20th FEB 2020
- Updated alternate components
- Mistral Design Team
- AJIT MB
- AJIT MB
- A
- 1.0
- 20th MAR 2020
- Baselined
- Mistral Design Team
- AJIT MB
- AJIT MB
sheet 4
- BLOCK DIAGRAM
sheet 5
- Serdes Connector
- Power Connector
- 12V to 3.3V @ 6.5A Supply
- PCIe Reset
- Short 1 and  2 for Device operation
  Short 3 and  2 for Host operation
- x4 Lane PCIe Connector
- Do Not Mount R216 and R298 for Host operation
  Mount R229, R213, R215, R299 and R243 for Host operation
  Do Not Maount  R229, R213, R215, R299 and R243 for Device operation
  Mount R216 and R298 for Device operation
sheet 6
- USB 2.0
- USB 2.0 micro AB Connector
- USB Power switch- 0.5A
- BOARD ID EEPROM
- I2C address: 0x54h or  Set by host
sheet 7
- 2 Lane PCIe Clock HCSL (100MHz) (EEPROM PAGE 0)
- CLOCK ROOT SELECTION
